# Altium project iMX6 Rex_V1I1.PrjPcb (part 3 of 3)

## Sheet [13] - ETHERNET PHY.SchDoc
size A2; DocumentNumber: 13; SheetNumber: 13; SheetTotal: 20
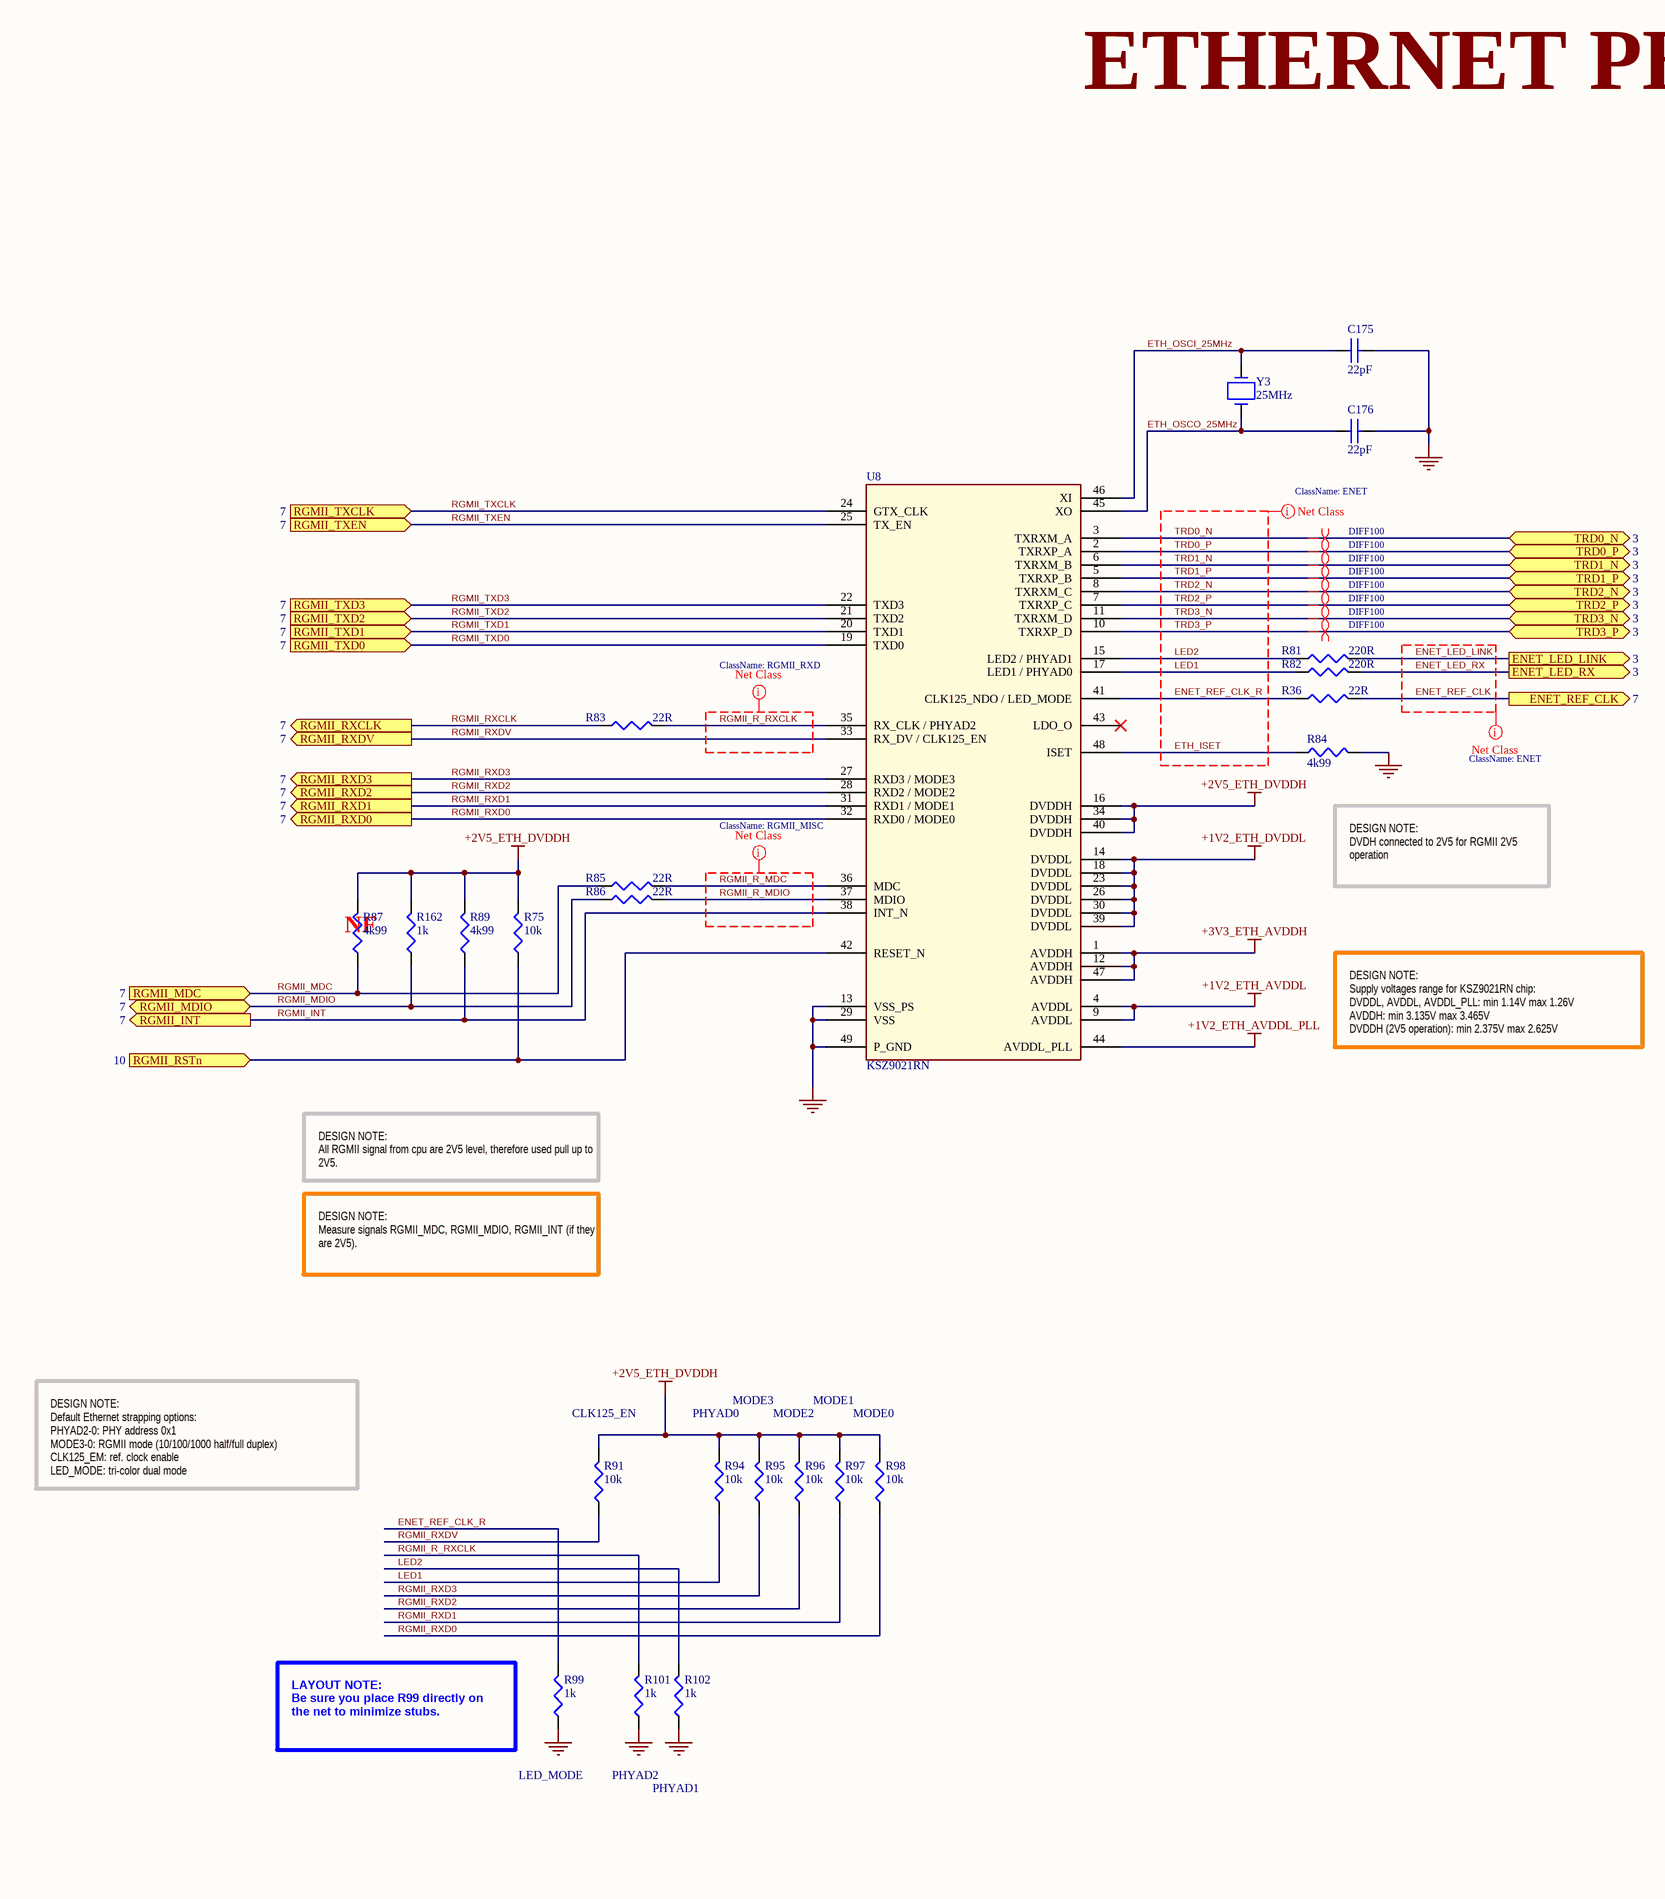
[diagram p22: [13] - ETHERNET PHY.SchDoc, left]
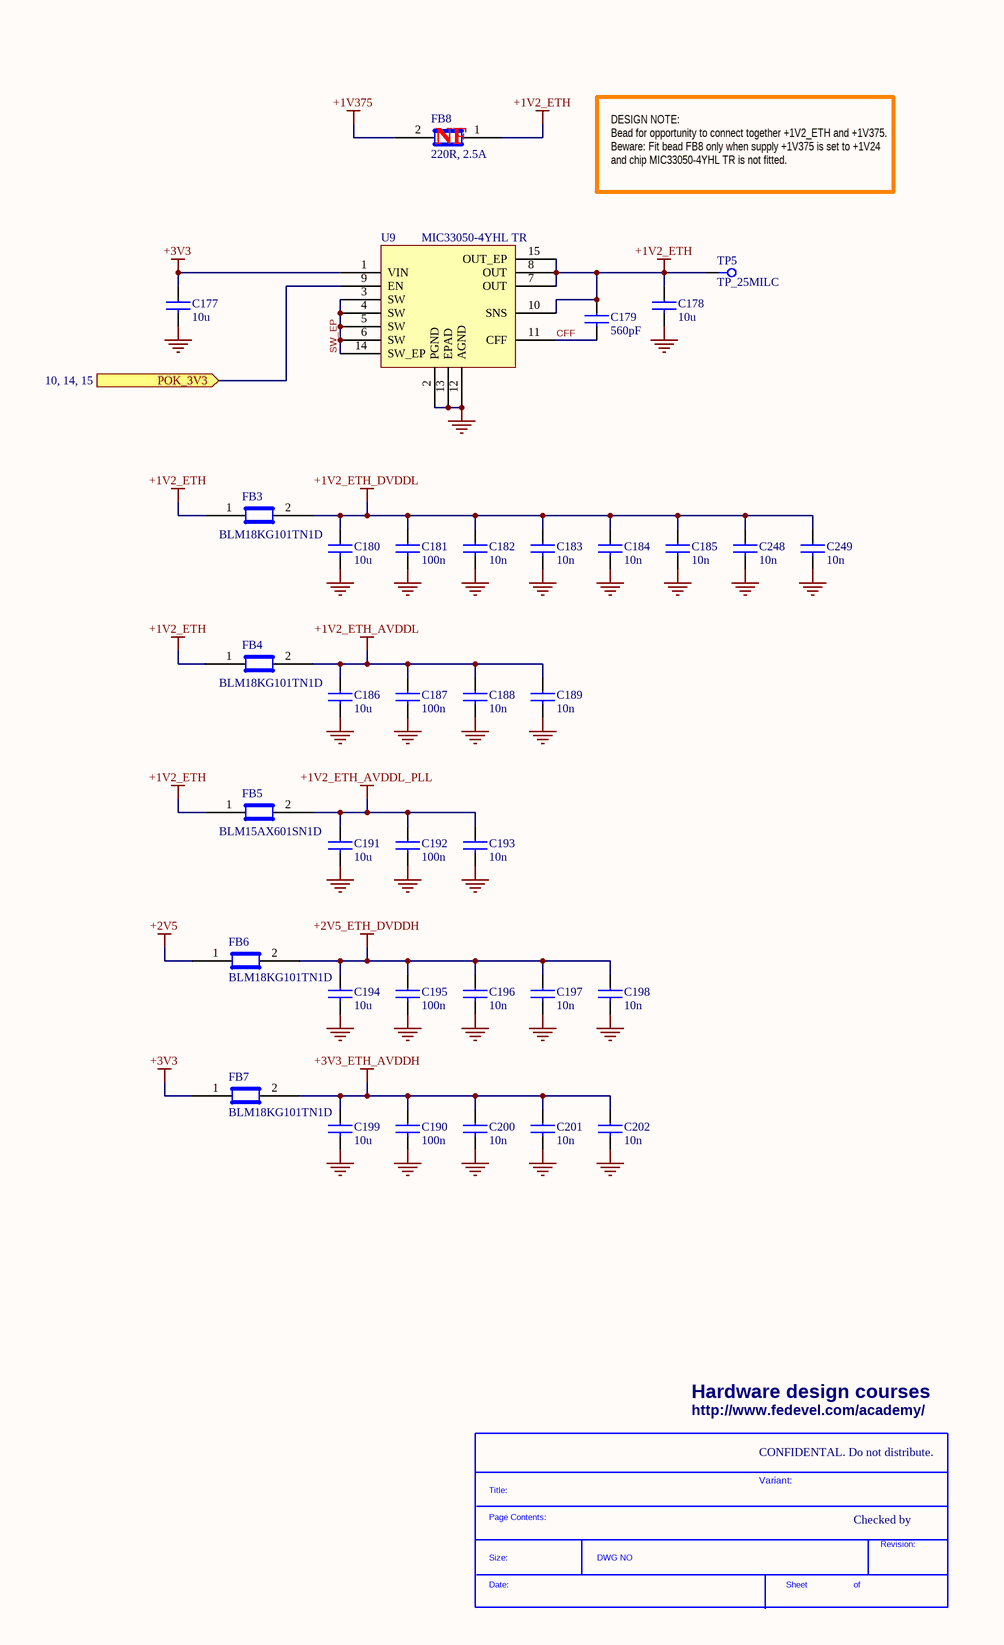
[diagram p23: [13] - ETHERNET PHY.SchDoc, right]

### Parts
(Parts that share a designator on the sheet are numbered #1, #2 ... from top to bottom, then left to right.)
*#15  SDTitleBlock  (value not drawn)  (graphical)
C175  22pF  [C0402]
C176  22pF  [C0402]
C177  10u  [C0603]
C178  10u  [C0603]
C179  560pF  [C0402]
C180  10u  [C0603]
C181  100n  [C0402]
C182  10n  [C0402]
C183  10n  [C0402]
C184  10n  [C0402]
C185  10n  [C0402]
C186  10u  [C0603]
C187  100n  [C0402]
C188  10n  [C0402]
C189  10n  [C0402]
C190  100n  [C0402]
C191  10u  [C0603]
C192  100n  [C0402]
C193  10n  [C0402]
C194  10u  [C0603]
C195  100n  [C0402]
C196  10n  [C0402]
C197  10n  [C0402]
C198  10n  [C0402]
C199  10u  [C0603]
C200  10n  [C0402]
C201  10n  [C0402]
C202  10n  [C0402]
C248  10n  [C0402]
C249  10n  [C0402]
FB3  BLM18KG101TN1D  [C0603]
FB4  BLM18KG101TN1D  [C0603]
FB5  BLM15AX601SN1D  [C0402]
FB6  BLM18KG101TN1D  [C0603]
FB7  BLM18KG101TN1D  [C0603]
FB8  220R, 2.5A  [C0603]
R36  22R  [R0402]
R75  10k  [R0402]
R81  220R  [R0402]
R82  220R  [R0402]
R83  22R  [R0402]
R84  4k99  [R0402]
R85  22R  [R0402]
R86  22R  [R0402]
R87  4k99  [R0402]
R89  4k99  [R0402]
R91  10k  [R0402]
R94  10k  [R0402]
R95  10k  [R0402]
R96  10k  [R0402]
R97  10k  [R0402]
R98  10k  [R0402]
R99  1k  [R0402]
R101  1k  [R0402]
R102  1k  [R0402]
R162  1k  [R0402]
TP5  TP_25MILC  [TP_25C]  (no BOM)
U8  KSZ9021RN  [QFN48_7MMX7MM]
U9  MIC33050-4YHL TR  [MLF_3x3_12PINS]
Y3  25MHz  [ABM7_v1_1]

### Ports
ENET_LED_LINK (out, see 3), ENET_LED_RX (out, see 3), ENET_REF_CLK (out, see 7), POK_3V3 (see 10, 14, 15), RGMII_INT (out, see 7), RGMII_MDC (in, see 7), RGMII_MDIO (bidir, see 7), RGMII_RSTn (in, see 10), RGMII_RXCLK (out, see 7), RGMII_RXD0 (out, see 7), RGMII_RXD1 (out, see 7), RGMII_RXD2 (out, see 7), RGMII_RXD3 (out, see 7), RGMII_RXDV (out, see 7), RGMII_TXCLK (in, see 7), RGMII_TXD0 (in, see 7), RGMII_TXD1 (in, see 7), RGMII_TXD2 (in, see 7), RGMII_TXD3 (in, see 7), RGMII_TXEN (in, see 7), TRD0_N (bidir, see 3), TRD0_P (bidir, see 3), TRD1_N (bidir, see 3), TRD1_P (bidir, see 3), TRD2_N (bidir, see 3), TRD2_P (bidir, see 3), TRD3_N (bidir, see 3), TRD3_P (bidir, see 3)

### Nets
+1V2_ETH: C178.1 C179.1 FB3.1 FB4.1 FB5.1 FB8.1 TP5.1 U9.7(OUT) U9.8(OUT) U9.10(SNS) U9.15(OUT_EP)
+1V2_ETH_AVDDL: C186.1 C187.1 C188.1 C189.1 FB4.2 U8.4(AVDDL) U8.9(AVDDL)
+1V2_ETH_AVDDL_PLL: C191.1 C192.1 C193.1 FB5.2 U8.44(AVDDL_PLL)
+1V2_ETH_DVDDL: C180.1 C181.1 C182.1 C183.1 C184.1 C185.1 C248.1 C249.1 FB3.2 U8.14(DVDDL) U8.18(DVDDL) U8.23(DVDDL) U8.26(DVDDL) U8.30(DVDDL) U8.39(DVDDL)
+1V375: FB8.2
+2V5: FB6.1
+2V5_ETH_DVDDH: C194.1 C195.1 C196.1 C197.1 C198.1 FB6.2 R75.2 R87.2 R89.2 R91.2 R94.2 R95.2 R96.2 R97.2 R98.2 R162.2 U8.16(DVDDH) U8.34(DVDDH) U8.40(DVDDH)
+3V3: C177.1 FB7.1 U9.1(VIN)
+3V3_ETH_AVDDH: C190.1 C199.1 C200.1 C201.1 C202.1 FB7.2 U8.1(AVDDH) U8.12(AVDDH) U8.47(AVDDH)
GND: C175.2 C176.2 C177.2 C178.2 C180.2 C181.2 C182.2 C183.2 C184.2 C185.2 C186.2 C187.2 C188.2 C189.2 C190.2 C191.2 C192.2 C193.2 C194.2 C195.2 C196.2 C197.2 C198.2 C199.2 C200.2 C201.2 C202.2 C248.2 C249.2 R84.2 R99.1 R101.1 R102.1 U8.13(VSS_PS) U8.29(VSS) U8.49(P_GND) U9.2(PGND) U9.12(AGND) U9.13(EPAD)
CFF: C179.2 U9.11(CFF)
ENET_LED_LINK: R81.2 ; port ENET_LED_LINK
ENET_LED_RX: R82.2 ; port ENET_LED_RX
ENET_REF_CLK: R36.2 ; port ENET_REF_CLK
ENET_REF_CLK_R: R36.1 R99.2 U8.41(CLK125_NDO_/_LED_MODE)
ETH_ISET: R84.1 U8.48(ISET)
ETH_OSCI_25MHz: C175.1 U8.46(XI) Y3.2
ETH_OSCO_25MHz: C176.1 U8.45(XO) Y3.1
LED1: R82.1 R94.1 U8.17(LED1_/_PHYAD0)
LED2: R81.1 R102.2 U8.15(LED2_/_PHYAD1)
POK_3V3: U9.9(EN) ; port POK_3V3
RGMII_INT: R89.1 U8.38(INT_N) ; port RGMII_INT
RGMII_MDC: R85.1 R87.1 ; port RGMII_MDC
RGMII_MDIO: R86.1 R162.1 ; port RGMII_MDIO
RGMII_R_MDC: R85.2 U8.36(MDC)
RGMII_R_MDIO: R86.2 U8.37(MDIO)
RGMII_R_RXCLK: R83.2 R101.2 U8.35(RX_CLK_/_PHYAD2)
RGMII_RSTn: R75.1 U8.42(RESET_N) ; port RGMII_RSTn
RGMII_RXCLK: R83.1 ; port RGMII_RXCLK
RGMII_RXD0: R98.1 U8.32(RXD0_/_MODE0) ; port RGMII_RXD0
RGMII_RXD1: R97.1 U8.31(RXD1_/_MODE1) ; port RGMII_RXD1
RGMII_RXD2: R96.1 U8.28(RXD2_/_MODE2) ; port RGMII_RXD2
RGMII_RXD3: R95.1 U8.27(RXD3_/_MODE3) ; port RGMII_RXD3
RGMII_RXDV: R91.1 U8.33(RX_DV_/_CLK125_EN) ; port RGMII_RXDV
RGMII_TXCLK: U8.24(GTX_CLK) ; port RGMII_TXCLK
RGMII_TXD0: U8.19(TXD0) ; port RGMII_TXD0
RGMII_TXD1: U8.20(TXD1) ; port RGMII_TXD1
RGMII_TXD2: U8.21(TXD2) ; port RGMII_TXD2
RGMII_TXD3: U8.22(TXD3) ; port RGMII_TXD3
RGMII_TXEN: U8.25(TX_EN) ; port RGMII_TXEN
SW_EP: U9.3(SW) U9.4(SW) U9.5(SW) U9.6(SW) U9.14(SW_EP)
TRD0_N: U8.3(TXRXM_A) ; port TRD0_N
TRD0_P: U8.2(TXRXP_A) ; port TRD0_P
TRD1_N: U8.6(TXRXM_B) ; port TRD1_N
TRD1_P: U8.5(TXRXP_B) ; port TRD1_P
TRD2_N: U8.8(TXRXM_C) ; port TRD2_N
TRD2_P: U8.7(TXRXP_C) ; port TRD2_P
TRD3_N: U8.11(TXRXM_D) ; port TRD3_N
TRD3_P: U8.10(TXRXP_D) ; port TRD3_P

Not connected (* = marked no-connect by the designer): U8 43(LDO_O)*

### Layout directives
differential pair; net class DIFF100: TRD0_N, TRD0_P, TRD1_N, TRD1_P, TRD2_N, TRD2_P, TRD3_N, TRD3_P
net class ENET: ENET_LED_LINK, ENET_LED_RX, ENET_REF_CLK, ENET_REF_CLK_R, ETH_ISET, LED1, LED2, TRD0_N, TRD0_P, TRD1_N, TRD1_P, TRD2_N, TRD2_P, TRD3_N, TRD3_P
net class RGMII_MISC: RGMII_R_MDC, RGMII_R_MDIO
net class RGMII_RXD: RGMII_R_RXCLK

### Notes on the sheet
- ETHERNET PHY
- (near FB8) NF
- DESIGN NOTE:
  Bead for opportunity to connect together +1V2_ETH and +1V375. Beware: Fit bead FB8 only when supply +1V375 is set to +1V24 and chip MIC33050-4YHL TR is not fitted.
- DESIGN NOTE:
  DVDH connected to 2V5 for RGMII 2V5 operation
- (near R87) NF
- DESIGN NOTE:
  Supply voltages range for KSZ9021RN chip:
  DVDDL, AVDDL, AVDDL_PLL: min 1.14V max 1.26V
  AVDDH: min 3.135V max 3.465V
  DVDDH (2V5 operation): min 2.375V max 2.625V
- DESIGN NOTE:
  All RGMII signal from cpu are 2V5 level, therefore used pull up to 2V5.
- DESIGN NOTE:
  Measure signals RGMII_MDC, RGMII_MDIO, RGMII_INT (if they are 2V5).
- (near R91) CLK125_EN
- PHYAD0
- MODE3
- MODE2
- MODE1
- MODE0
- DESIGN NOTE:
  Default Ethernet strapping options:
  PHYAD2-0: PHY address 0x1
  MODE3-0: RGMII mode (10/100/1000 half/full duplex)
  CLK125_EM: ref. clock enable
  LED_MODE: tri-color dual mode
- LAYOUT NOTE:
  Be sure you place R99 directly on the net to minimize stubs.
- LED_MODE
- PHYAD2
- Hardware design courses
- PHYAD1
- http://www.fedevel.com/academy/
- CONFIDENTAL. Do not distribute.
- Variant:
- Checked by

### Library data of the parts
C175 C176 = C1005C0G1H220J: CAP CER 22PF 50V C0G 5% 0402; Manufacturer: TDK Corporation; .Checked PCB: used; Description: CAP CER 22PF 50V 5% NP0 0402; Temperature Coefficient: C0G, NP0
C177 C178 C180 C186 C191 C194 C199 = C1608X5R0J106M: CAP CER 10UF 6.3V X5R 20% 0603; Manufacturer: TDK Corporation; Capacitance: 10µF; Value: 10µF; .Checked PCB: used; Description: CAP CER 10UF 6.3V 20% X5R 0603
C179 = GRM1555C1H561JA01D: CAP CER 560PF 50V C0G 0402; Manufacturer: Murata Electronics North America; .Checked PCB: used; Description: CAP CER 560PF 50V 5% NP0 0402; Tolerance: ±5%; Temperature Coefficient: C0G, NP0
C181 C187 C190 C192 C195 = C1005X5R1H104K: CAP CER .10UF 50V X5R 10% 0402; Manufacturer: TDK Corporation; Capacitance: 0.1µF; Value: 100nF; .Checked PCB: used; Description: CAP CER 0.1UF 50V 10% X5R 0402
C182-C185 C188 C189 C193 C196-C198 C200-C202 C248 C249 = C1005X7R1C103K: CAP CER 10000PF 16V X7R 10% 0402; Manufacturer: TDK Corporation; Value: 10nF; .Checked PCB: used; Description: CAP CER 10000PF 16V 10% X7R 0402
FB3 FB4 FB6 FB7 = BLM18KG101TN1D: FERRITE CHIP 100 OHM BEAD 0603 3A; Manufacturer: Murata Electronics North America; .Checked PCB: used; Impedance @ Frequency: 100 Ohm @ 100MHz; DC Resistance (DCR): 30 mOhm Max; Filter Type: Differential Mode - Single; Number of Lines: 1
FB5 = BLM15AX601SN1D: FERRITE CHIP 600 OHM 0402 420mA; Manufacturer: Murata Electronics North America; .Checked PCB: used; Impedance @ Frequency: 600 Ohm @ 100MHz; DC Resistance (DCR): 340 mOhm Max; Filter Type: Differential Mode - Single; Number of Lines: 1
FB8 = BLM18SG221TN1D: FERRITE CHIP 220 OHM 2500MA 0603; Manufacturer: Murata Electronics North America; Impedance @ Frequency: 220 Ohm @ 100MHz; DC Resistance (DCR): 40 mOhm Max; Filter Type: Differential Mode - Single; Number of Lines: 1; .Checked PCB: RF
R36 R83 R85 R86 = RC0402FR-0722RL: RES 22.0 OHM 1/16W 1% 0402 SMD; Manufacturer: Yageo; Resistance (Ohms): 22; Power (Watts): 0.063W, 1/16W; .Checked PCB: used; Temperature Coefficient: ±100ppm/°C
R75 R91 R94-R98 = RC0402FR-0710KL: RES 10.0K OHM 1/16W 1% 0402 SMD; Manufacturer: Yageo; Power (Watts): 0.063W, 1/16W; .Checked PCB: used; Temperature Coefficient: ±100ppm/°C
R81 R82 = RC0402FR-07220RL: RES 220 OHM 1/16W 1% 0402 SMD; Manufacturer: Yageo; Resistance (Ohms): 220; Power (Watts): 0.063W, 1/16W; .Checked PCB: used; Temperature Coefficient: ±100ppm/°C
R84 R87 R89 = RMCF0402FT4K99: RES TF 4.99K OHM 1% 1/16W 0402; Manufacturer: Stackpole Electronics Inc; Power (Watts): 0.063W, 1/16W; .Checked PCB: used; Temperature Coefficient: ±100ppm/°C
R99 R101 R102 R162 = RC0402FR-071KL: RES 1.00K OHM 1/16W 1% 0402 SMD; Manufacturer: Yageo; Power (Watts): 0.063W, 1/16W; .Checked PCB: used; Temperature Coefficient: ±100ppm/°C
TP5 = TP_25MILC: Test Point 25mil
U8 = KSZ9021RN: IC TXRX 10/100/1000 SGL 48QFN; Manufacturer: Micrel Inc; Number of Drivers/Receivers: 8/8; Protocol: Gigabit Ethernet; Voltage - Supply: 3.135 V ~ 3.465 V; .Creator: MM; .Checked PCB: MM, checked by RF
U9 = MIC33050-4YHL TR: IC PWM REG 600mA 1.2V 12-MLF; Manufacturer: Micrel Inc; .Checked PCB: used; Voltage - Input: 2.7 V ~ 5.5 V; Description: IC BUCK SYNC 1.2V 0.6A 12MLF; Output Type: Fixed; Number of Outputs: 1; PWM Type: Current Mode; Frequency - Switching: 4MHz; Synchronous Rectifier: Yes
Y3 = ABM7-25.000MHZ-D-2-Y-T V1.1: CRYSTAL 25.0000 MHZ 18PF SMD; Manufacturer: Abracon Corporation; .Checked PCB: RF used by MM; Frequency Stability: ±30ppm; Frequency Tolerance: ±20ppm; Operating Mode: Fundamental; .V1.1: footprint & comment updated

## Sheet [14] - SPI FLASH, LEDS.SchDoc
size A2; DocumentNumber: 14; SheetNumber: 14; SheetTotal: 20
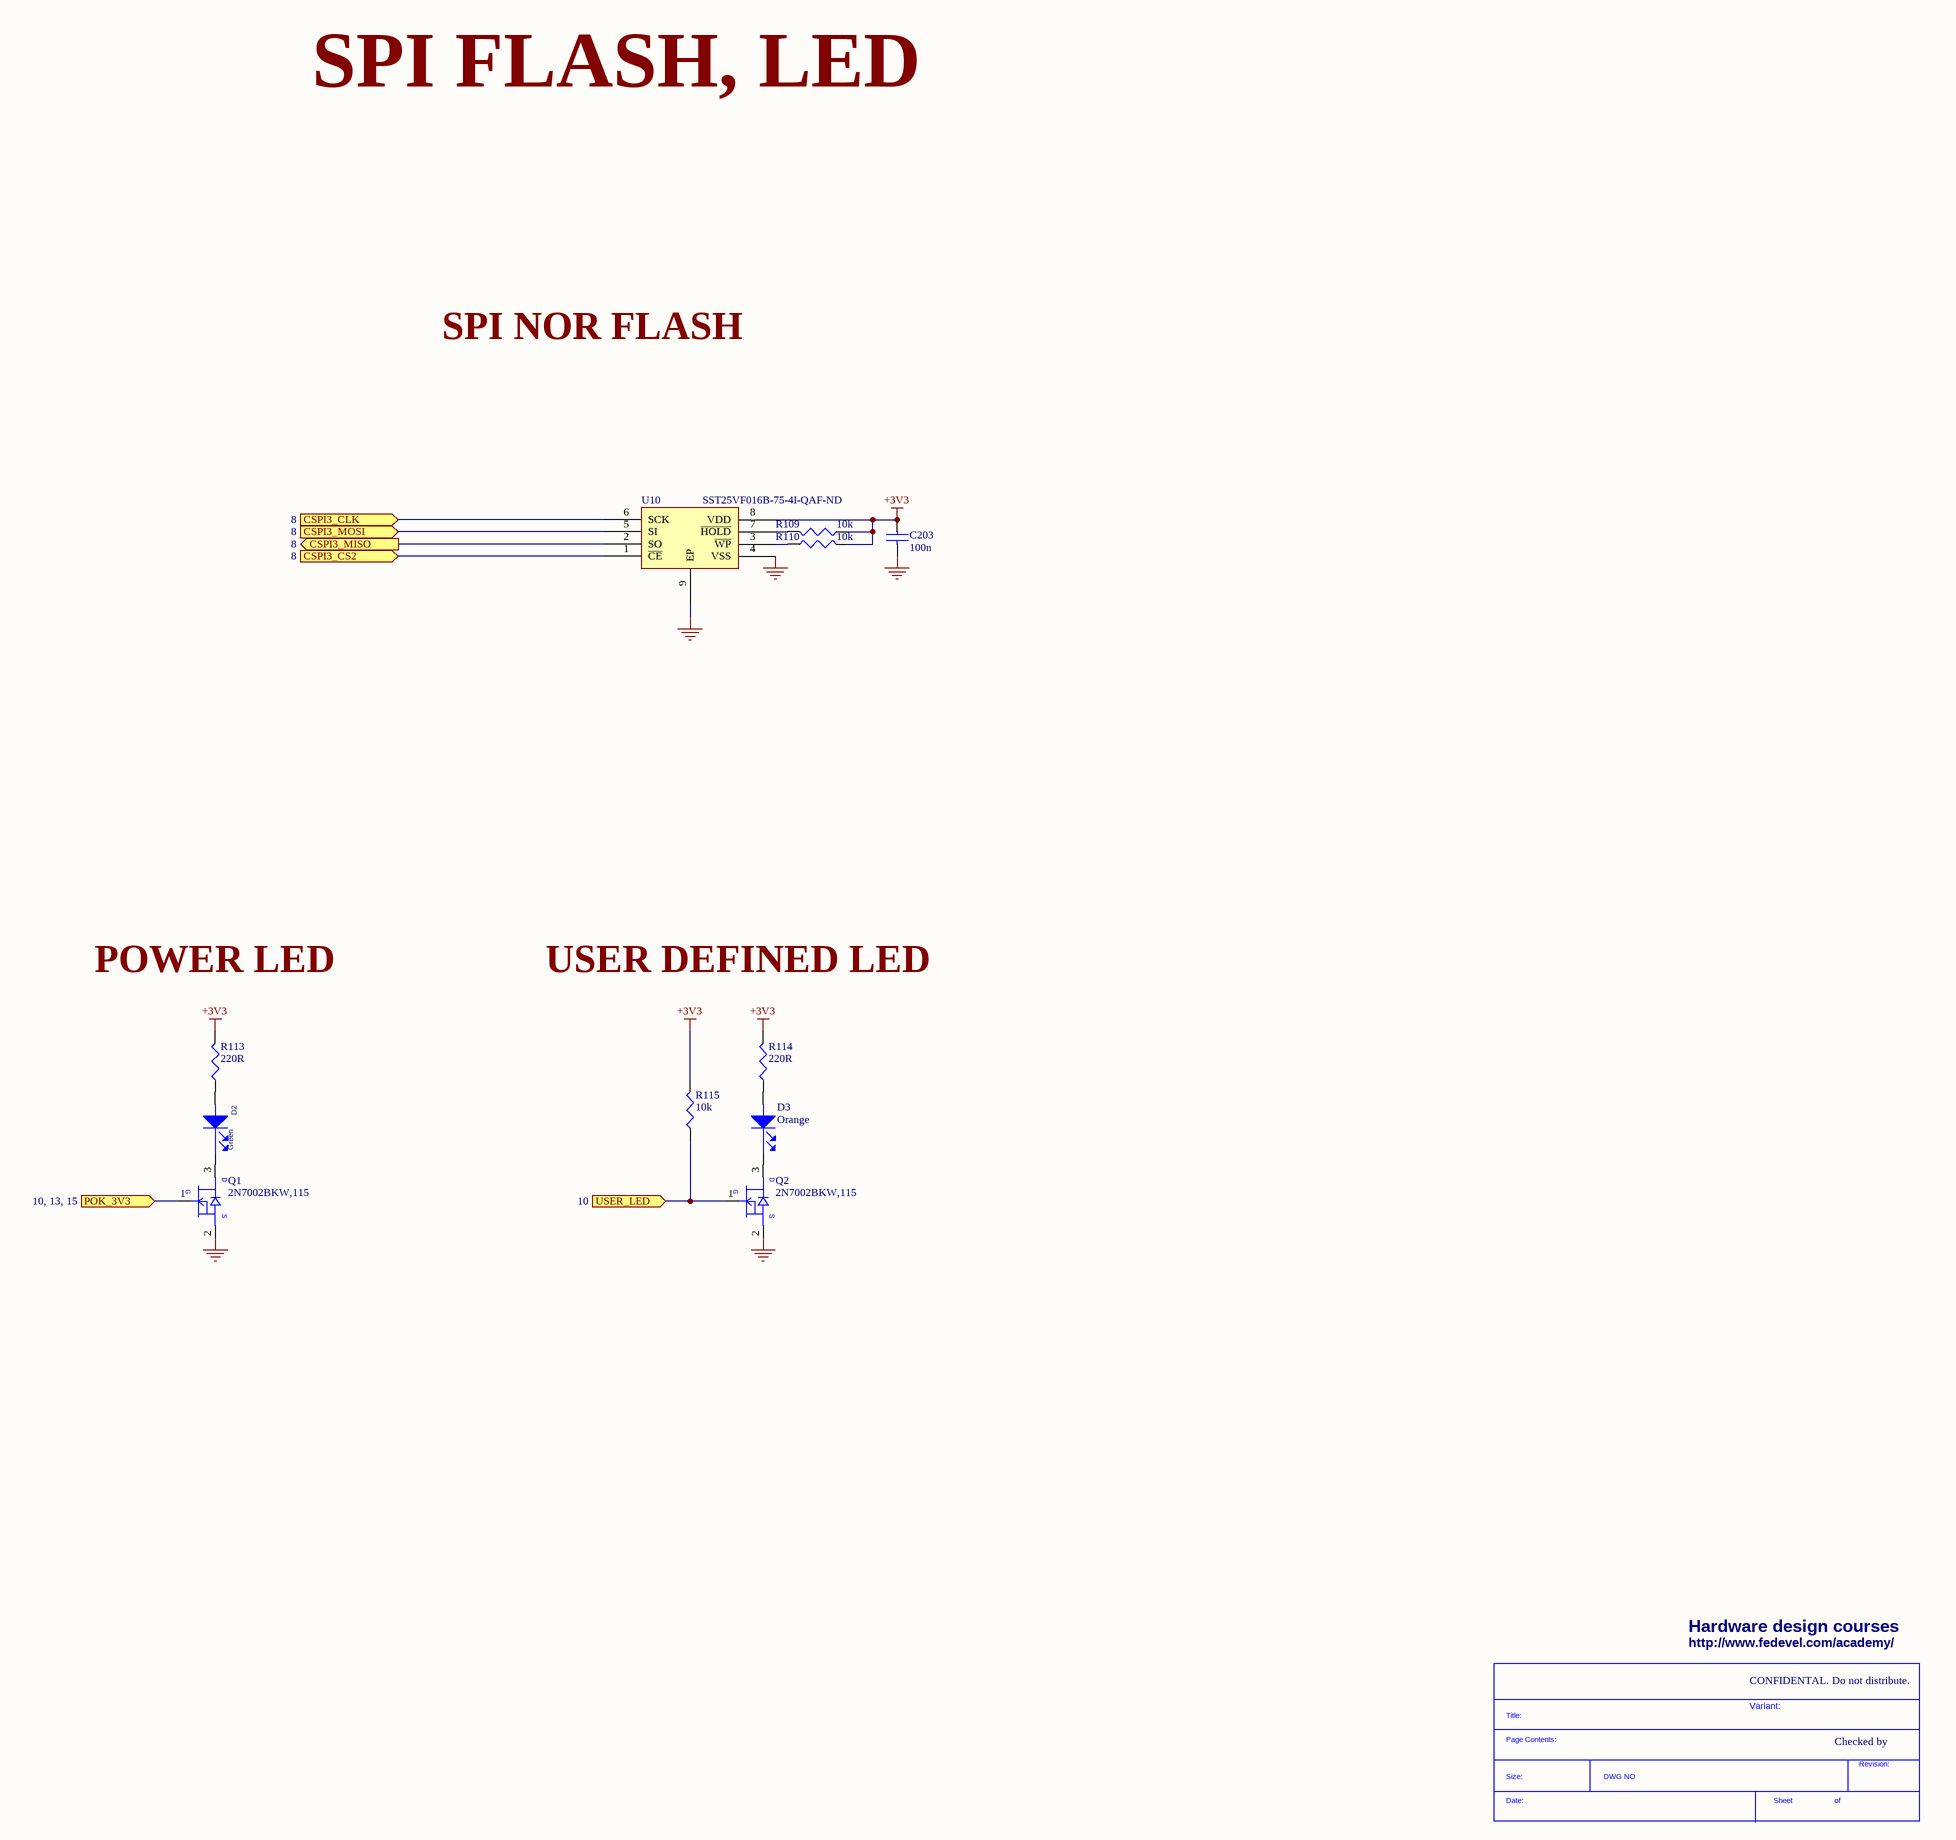
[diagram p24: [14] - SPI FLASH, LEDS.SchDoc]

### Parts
(Parts that share a designator on the sheet are numbered #1, #2 ... from top to bottom, then left to right.)
*#16  SDTitleBlock  (value not drawn)  (graphical)
C203  100n  [C0402]
D2  Green  [LED_0603]
D3  Orange  [LED_0603]
Q1  2N7002BKW,115  [SC70_SOT323]
Q2  2N7002BKW,115  [SC70_SOT323]
R109  10k  [R0402]
R110  10k  [R0402]
R113  220R  [R0402]
R114  220R  [R0402]
R115  10k  [R0402]
U10  SST25VF016B-75-4I-QAF-ND  [WSON8_6X5MM]

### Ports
CSPI3_CLK (in, see 8), CSPI3_CS2 (in, see 8), CSPI3_MISO (out, see 8), CSPI3_MOSI (in, see 8), POK_3V3 (see 10, 13, 15), USER_LED (in, see 10)

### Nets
+3V3: C203.1 R109.1 R110.2 R113.2 R114.2 R115.2 U10.8(VDD)
GND: C203.2 Q1.2(SOURCE) Q2.2(SOURCE) U10.4(VSS) U10.9(EP)
CSPI3_CLK: U10.6(SCK) ; port CSPI3_CLK
CSPI3_CS2: U10.1(~{CE}) ; port CSPI3_CS2
CSPI3_MISO: U10.2(SO) ; port CSPI3_MISO
CSPI3_MOSI: U10.5(SI) ; port CSPI3_MOSI
POK_3V3: Q1.1(GATE) ; port POK_3V3
USER_LED: Q2.1(GATE) R115.1 ; port USER_LED
NetD2_1: D2.1(cathode) Q1.3(DRAIN)
NetD2_2: D2.2(ANODE) R113.1
NetD3_1: D3.1(cathode) Q2.3(DRAIN)
NetD3_2: D3.2(ANODE) R114.1
NetR109_2: R109.2 U10.7(~{HOLD})
NetR110_1: R110.1 U10.3(~{WP})

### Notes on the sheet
- SPI FLASH, LED
- SPI NOR FLASH
- POWER LED
- USER DEFINED LED
- Hardware design courses
- http://www.fedevel.com/academy/
- CONFIDENTAL. Do not distribute.
- Variant:
- Checked by

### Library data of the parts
C203 = C1005X5R1H104K: as C181 on sheet [13] - ETHERNET PHY
D2 = LG L29K-G2J1-24-Z: LED SMARTLED GREEN 570NM 0603; Manufacturer: OSRAM Opto Semiconductors Inc; .Checked PCB: used; Current - Test: 2mA; Voltage - Forward (Vf) Typ: 1.7V; Luminous Flux @ Current - Test: 12 mlm; Millicandela Rating: 3.92mcd; Wavelength - Peak: 572nm; Lens Type: Diffused; Lens Style/Size: Rectangle with Flat Top, 1.3mm x 0.8mm; Viewing Angle: 160°; Regulator Topology: Positive Fixed; Voltage - Output: 2.5V; Voltage - Input: 2.6 V ~ 6 V; Voltage - Dropout (Typical): 0.16V @ 500mA; Number of Regulators: 1; Current - Output: 500mA; Current - Limit (Min): 600mA
D3 = LO L29K-H2K1-24-Z: LED SMARTLED ORANGE 606NM 0603; Manufacturer: OSRAM Opto Semiconductors Inc; Millicandela Rating: 6.3mcd; Voltage - Forward (Vf) Typ: 1.8V; Current - Test: 2mA; Wavelength - Peak: 610nm; Viewing Angle: 160°; Lens Type: Diffused; Lens Style/Size: Rectangle with Flat Top, 1.3mm x 0.8mm; Luminous Flux @ Current - Test: 25 mlm; .Checked PCB: RF
Q1 Q2 = 2N7002BKW,115: MOSFET N-CH 60V 310MA SOT323; Manufacturer: NXP Semiconductors; FET Type: MOSFET N-Channel, Metal Oxide; FET Feature: Logic Level Gate; Rds On (Max) @ Id, Vgs: 1.6 Ohm @ 500mA, 10V; Vgs(th) (Max) @ Id: 2.1V @ 250µA; Gate Charge (Qg) @ Vgs: 0.6nC @ 4.5V; Input Capacitance (Ciss) @ Vds: 50pF @ 10V; Power - Max: 275mW; .Checked PCB: RF
R109 R110 R115 = RC0402FR-0710KL: as R75 on sheet [13] - ETHERNET PHY
R113 R114 = RC0402FR-07220RL: as R81 on sheet [13] - ETHERNET PHY
U10 = SST25VF016B-75-4I-QAF: IC FLASH 16MBIT 75MHZ 8WSON; Manufacturer: Microchip Technology; Memory Size: 16M (2M x 8); Interface: SPI Serial; Voltage - Supply: 2.7 V ~ 3.6 V; .Creator: MM; .Checked PCB: MM, checked by RF

## Sheet [15] - PWR 3V3, 1V375.SchDoc
size A2; DocumentNumber: 15; SheetNumber: 15; SheetTotal: 20
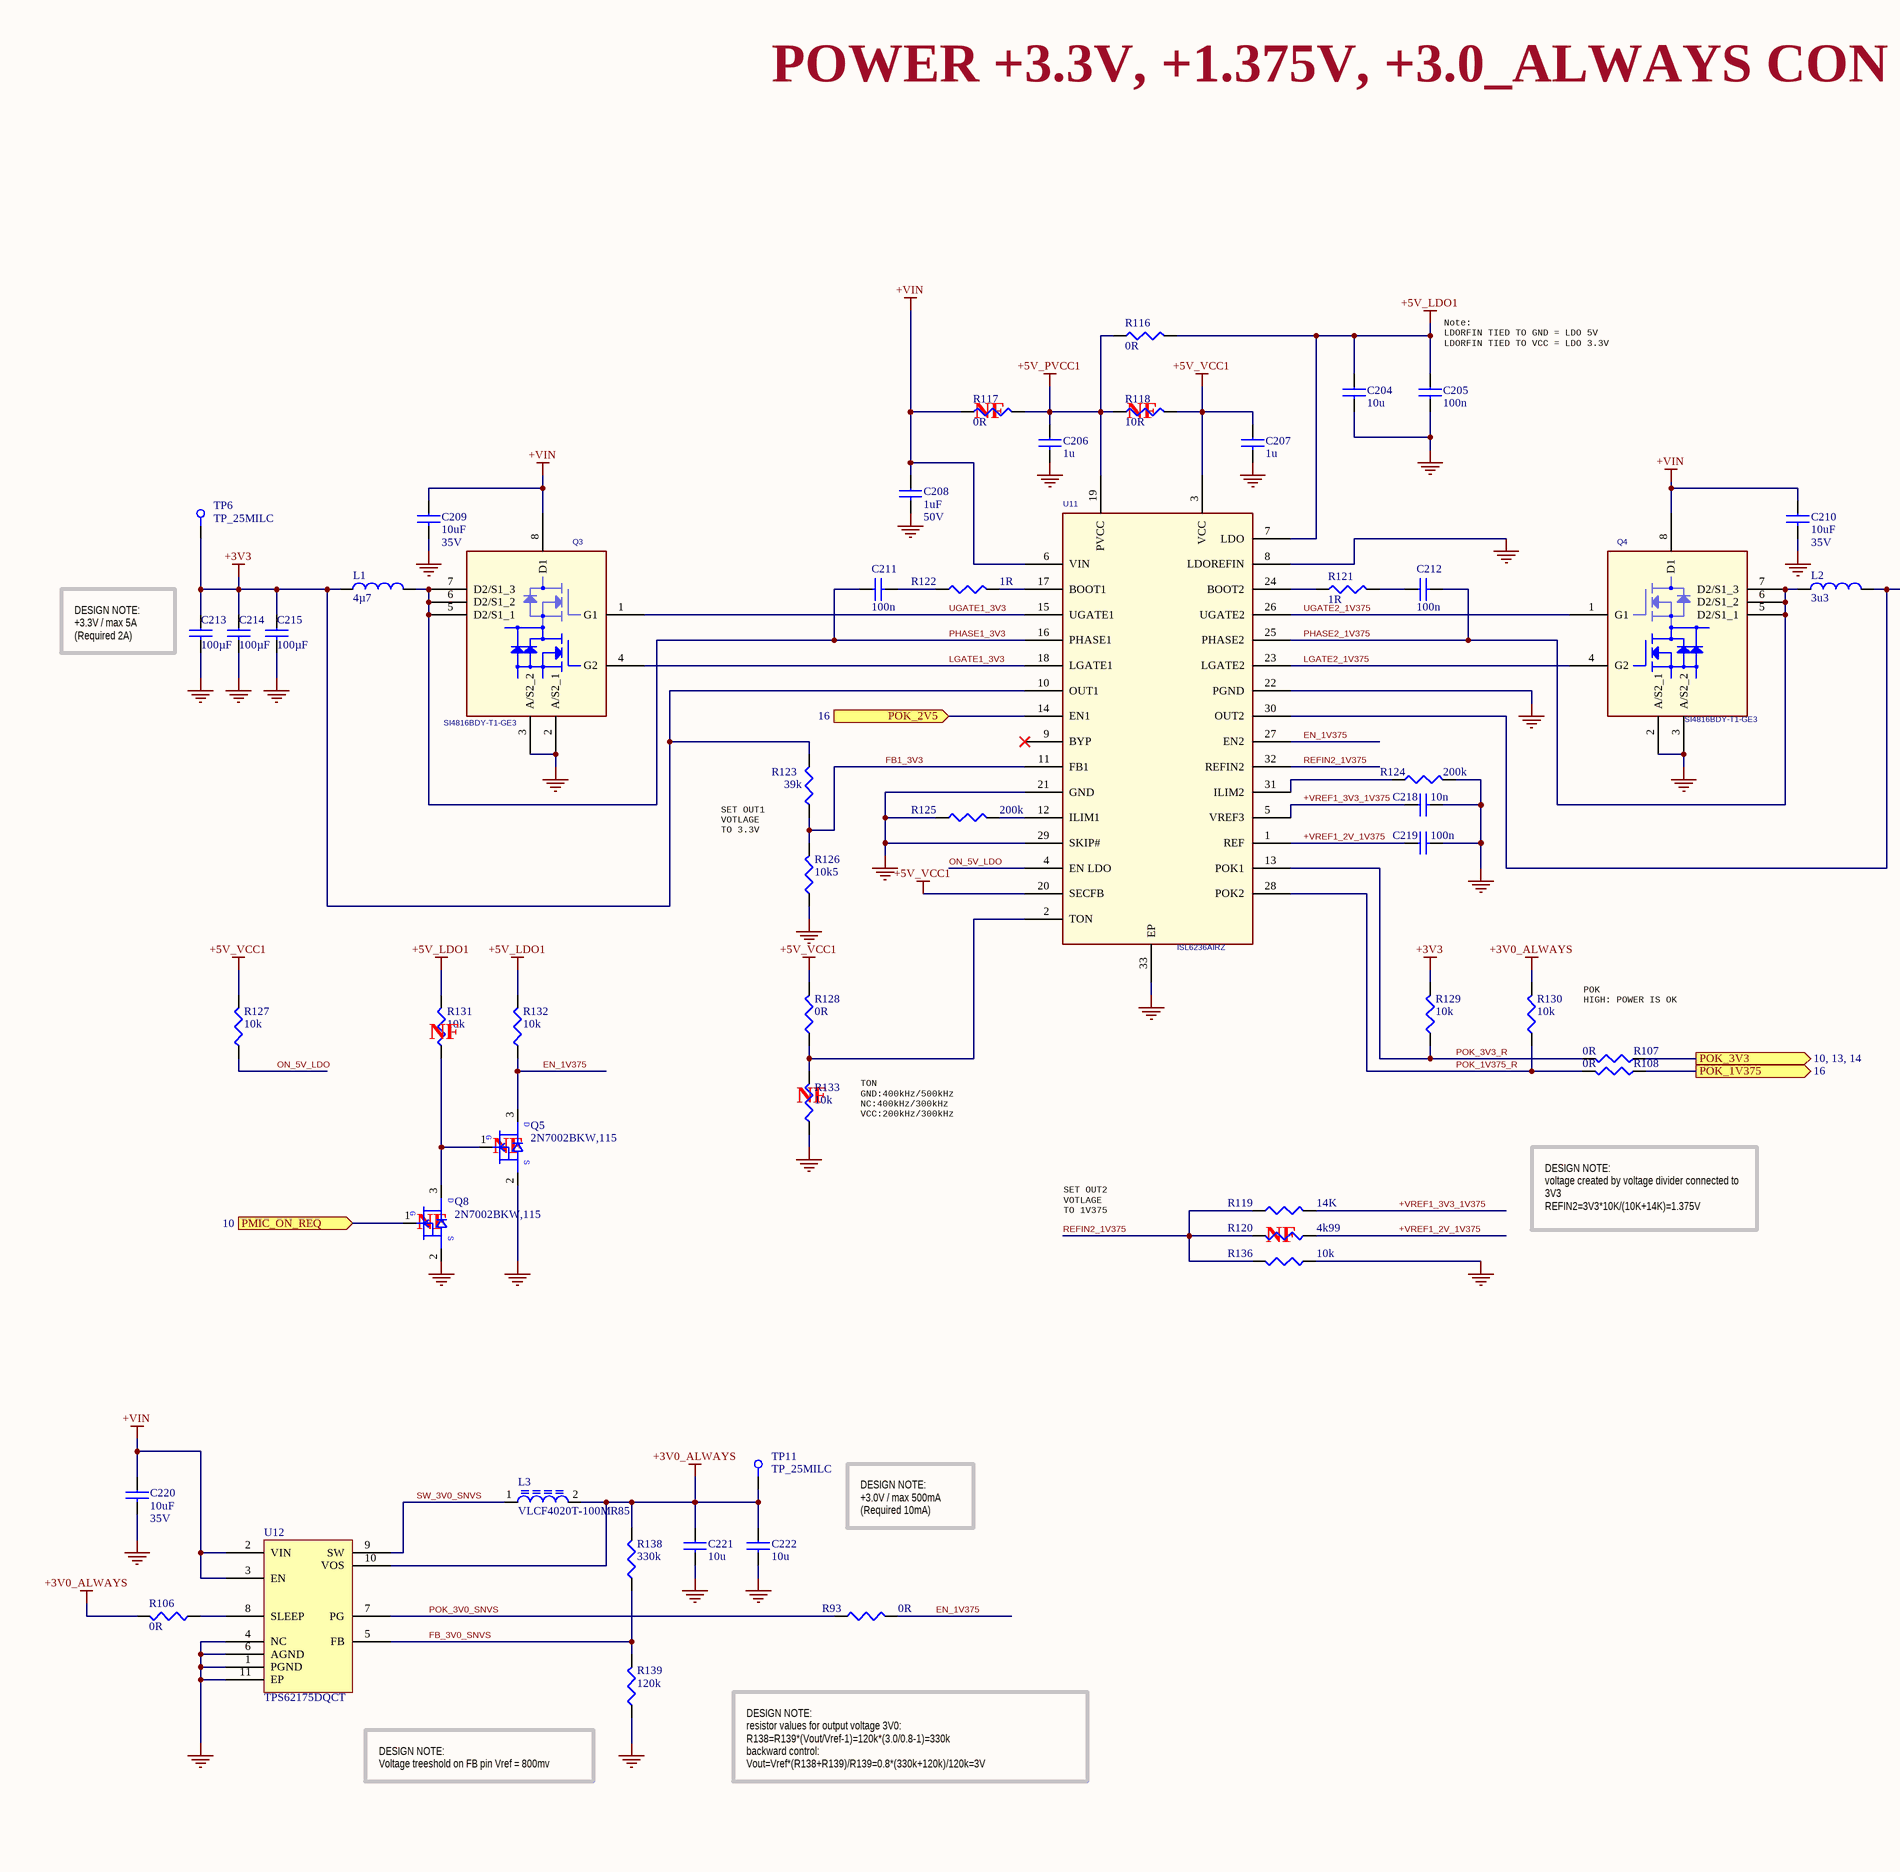
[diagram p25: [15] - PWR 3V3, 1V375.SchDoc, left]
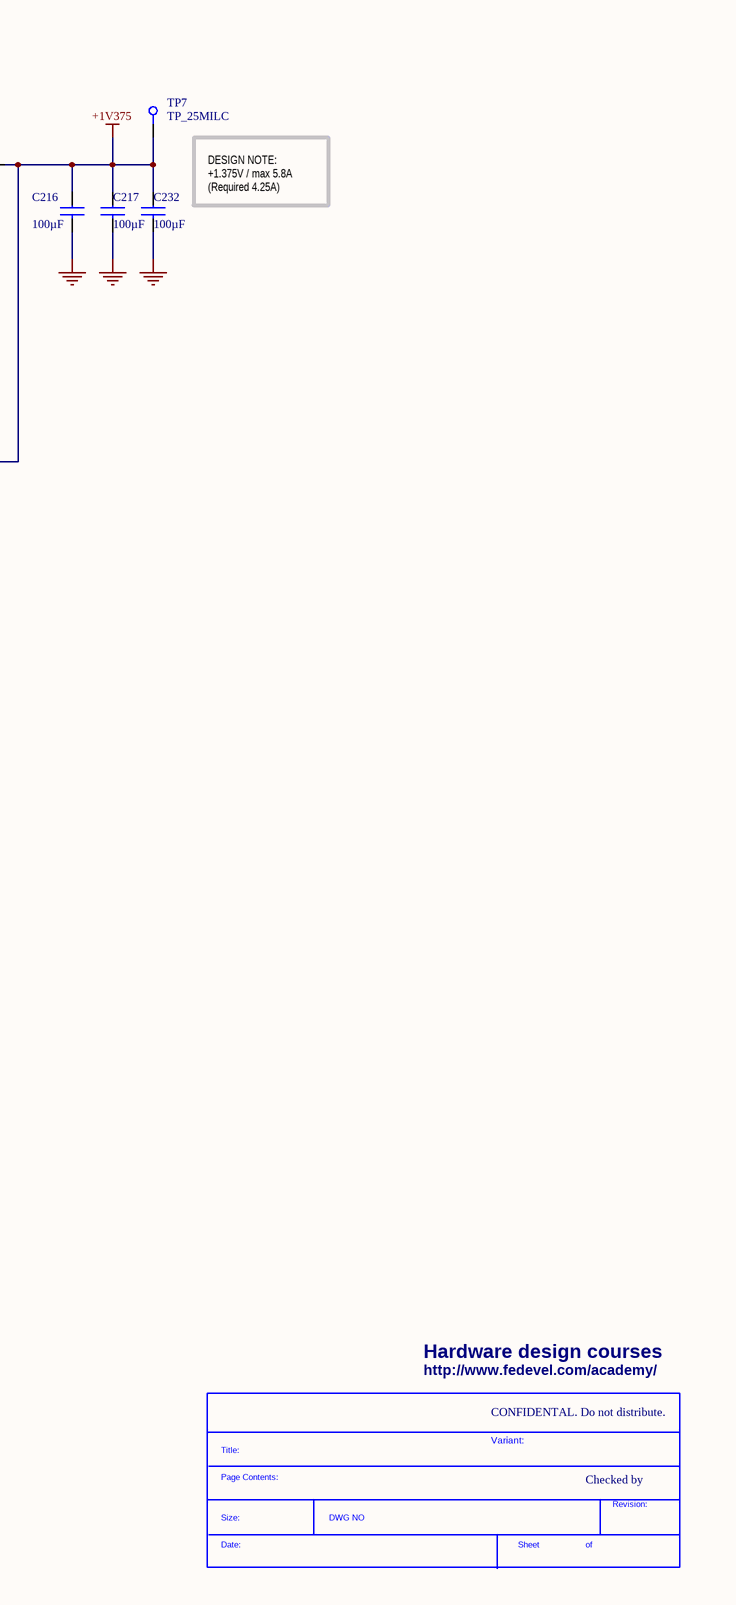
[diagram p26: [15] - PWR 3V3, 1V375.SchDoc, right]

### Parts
(Parts that share a designator on the sheet are numbered #1, #2 ... from top to bottom, then left to right.)
*#17  SDTitleBlock  (value not drawn)  (graphical)
C204  10u  [C0603]
C205  100n  [C0402]
C206  1u  [C0402]
C207  1u  [C0402]
C208  1uF  Voltage - Rated: 50V  [C0805]
C209  10uF  Voltage - Rated: 35V  [C1206]
C210  10uF  Voltage - Rated: 35V  [C1206]
C211  100n  [C0402]
C212  100n  [C0402]
C213  100µF  [C1206]
C214  100µF  [C1206]
C215  100µF  [C1206]
C216  100µF  [C1206]
C217  100µF  [C1206]
C218  10n  [C0402]
C219  100n  [C0402]
C220  10uF  Voltage - Rated: 35V  [C1206]
C221  10u  [C0603]
C222  10u  [C0603]
C232  100µF  [C1206]
L1  4µ7  [IHLP_255MILx270MIL]
L2  3u3  [IHLP_255MILx270MIL]
L3  VLCF4020T-100MR85  [VLCF4020]
Q3  SI4816BDY-T1-GE3  [8_SOIC_3.9MM]
Q4  SI4816BDY-T1-GE3  [8_SOIC_3.9MM]
Q5  2N7002BKW,115  [SC70_SOT323]
Q8  2N7002BKW,115  [SC70_SOT323]
R93  0R  [R0402]
R106  0R  [R0402]
R107  0R  [R0402]
R108  0R  [R0402]
R116  0R  [R0402]
R117  0R  [R0402]
R118  10R  [R0402]
R119  14K  [R0402]
R120  4k99  [R0402]
R121  1R  [R0402]
R122  1R  [R0402]
R123  39k  [R0402]
R124  200k  [R0402]
R125  200k  [R0402]
R126  10k5  [R0402]
R127  10k  [R0402]
R128  0R  [R0402]
R129  10k  [R0402]
R130  10k  [R0402]
R131  10k  [R0402]
R132  10k  [R0402]
R133  10k  [R0402]
R136  10k  [R0402]
R138  330k  [R0402]
R139  120k  [R0402]
TP6  TP_25MILC  [TP_25C]  (no BOM)
TP7  TP_25MILC  [TP_25C]  (no BOM)
TP11  TP_25MILC  [TP_25C]  (no BOM)
U11  ISL6236AIRZ  [32_VFQFN_EXPOSED_PAD]
U12  TPS62175DQCT  [DQC_PWSON-N10]

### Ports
PMIC_ON_REQ (in, see 10), POK_1V375 (out, see 16), POK_2V5 (in, see 16), POK_3V3 (see 10, 13, 14)

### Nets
+1V375: C216.1 C217.1 C232.1 L2.2 TP7.1 U11.30(OUT2)
+3V0_ALWAYS: C221.1 C222.1 L3.2 R106.2 R130.2 R138.2 TP11.1 U12.10(VOS)
+3V3: C213.1 C214.1 C215.1 L1.1 R123.2 R129.2 TP6.1 U11.10(OUT1)
+5V_LDO1: C204.1 C205.1 R116.2 R131.2 R132.2 U11.7(LDO)
+5V_PVCC1: C206.1 R116.1 R117.2 R118.1 U11.19(PVCC)
+5V_VCC1: C207.1 R118.2 R127.2 R128.2 U11.3(VCC) U11.20(SECFB)
+VIN: C208.1 C209.1 C210.1 C220.1 Q3.8(D1) Q4.8(D1) R117.1 U11.6(VIN) U12.2(VIN) U12.3(EN)
GND: C204.2 C205.2 C206.2 C207.2 C208.2 C209.2 C210.2 C213.2 C214.2 C215.2 C216.2 C217.2 C218.2 C219.2 C220.2 C221.2 C222.2 C232.2 Q3.2(A/S2_1) Q3.3(A/S2_2) Q4.2(A/S2_1) Q4.3(A/S2_2) Q5.2(SOURCE) Q8.2(SOURCE) R124.2 R125.1 R126.1 R133.1 R136.1 R139.1 U11.8(LDOREFIN) U11.21(GND) U11.22(PGND) U11.29(SKIP#) U11.33(EP) U12.1(PGND) U12.4(NC) U12.6(AGND) U12.11(EP)
+VREF1_2V_1V375: C219.1 R120.1 U11.1(REF)
+VREF1_3V3_1V375: C218.1 R119.2 U11.5(VREF3)
EN_1V375: Q5.3(DRAIN) R93.2 R132.1 U11.27(EN2)
FB1_3V3: R123.1 R126.2 U11.11(FB1)
FB_3V0_SNVS: R138.1 R139.2 U12.5(FB)
LGATE1_3V3: Q3.4(G2) U11.18(LGATE1)
LGATE2_1V375: Q4.4(G2) U11.23(LGATE2)
ON_5V_LDO: R127.1 U11.4(EN_LDO)
PHASE1_3V3: C211.1 L1.2 Q3.5(D2/S1_1) Q3.6(D2/S1_2) Q3.7(D2/S1_3) U11.16(PHASE1)
PHASE2_1V375: C212.2 L2.1 Q4.5(D2/S1_1) Q4.6(D2/S1_2) Q4.7(D2/S1_3) U11.25(PHASE2)
PMIC_ON_REQ: Q8.1(GATE) ; port PMIC_ON_REQ
POK_1V375: R108.1 ; port POK_1V375
POK_1V375_R: R108.2 R130.1 U11.28(POK2)
POK_2V5: U11.14(EN1) ; port POK_2V5
POK_3V0_SNVS: R93.1 U12.7(PG)
POK_3V3: R107.1 ; port POK_3V3
POK_3V3_R: R107.2 R129.1 U11.13(POK1)
REFIN2_1V375: R119.1 R120.2 R136.2 U11.32(REFIN2)
SW_3V0_SNVS: L3.1 U12.9(SW)
UGATE1_3V3: Q3.1(G1) U11.15(UGATE1)
UGATE2_1V375: Q4.1(G1) U11.26(UGATE2)
NetC211_2: C211.2 R122.1
NetC212_1: C212.1 R121.2
NetQ5_1: Q5.1(GATE) Q8.3(DRAIN) R131.1
NetR106_1: R106.1 U12.8(SLEEP)
NetR121_1: R121.1 U11.24(BOOT2)
NetR122_2: R122.2 U11.17(BOOT1)
NetR124_1: R124.1 U11.31(ILIM2)
NetR125_2: R125.2 U11.12(ILIM1)
NetR128_1: R128.1 R133.2 U11.2(TON)

Not connected (* = marked no-connect by the designer): U11 9(BYP)*

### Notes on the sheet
- POWER +3.3V, +1.375V, +3.0_ALWAYS CON
- (near C205) Note:
  LDORFIN TIED TO GND = LDO 5V
  LDORFIN TIED TO VCC = LDO 3.3V
- (near R117) NF
- (near R118) NF
- (near C213) DESIGN NOTE:
  +3.3V / max 5A
  (Required 2A)
- DESIGN NOTE:
  +1.375V / max 5.8A
  (Required 4.25A)
- SET OUT1
  VOTLAGE
  TO 3.3V
- POK
  HIGH: POWER IS OK
- (near R131) NF
- (near R133) NF
- TON
  GND:400kHz/500kHz
  NC:400kHz/300kHz
  VCC:200kHz/300kHz
- (near Q5) NF
- (near Q8) NF
- SET OUT2
  VOTLAGE
  TO 1V375
- (near R120) NF
- DESIGN NOTE:
  voltage created by voltage divider connected to 3V3
  REFIN2=3V3*10K/(10K+14K)=1.375V
- DESIGN NOTE:
  +3.0V / max 500mA
  (Required 10mA)
- Hardware design courses
- DESIGN NOTE:
  Voltage treeshold on FB pin Vref = 800mv
- DESIGN NOTE:
  resistor values for output voltage 3V0:
  R138=R139*(Vout/Vref-1)=120k*(3.0/0.8-1)=330k
  backward control:
  Vout=Vref*(R138+R139)/R139=0.8*(330k+120k)/120k=3V
- http://www.fedevel.com/academy/
- CONFIDENTAL. Do not distribute.
- Variant:
- Checked by

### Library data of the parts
C204 C221 C222 = C1608X5R0J106M: as C177 on sheet [13] - ETHERNET PHY
C205 C211 C212 C219 = C1005X5R1H104K: as C181 on sheet [13] - ETHERNET PHY
C206 C207 = C1005X5R1C105K: CAP CER 1.0UF 16V X5R 0402; Manufacturer: TDK Corporation; Capacitance: 1.0µF; Value: 1uF; .Checked PCB: used; Description: CAP CER 1UF 16V 10% X5R 0402; Tolerance: ±10%
C208 = GRM21BR71H105KA12L: CAP CER 1UF 50V X7R 0805; Manufacturer: Murata Electronics North America; Capacitance: 1.0µF; .Checked PCB: used; Description: CAP CER 1UF 50V 10% X7R 0805; Tolerance: ±10%
C209 C210 C220 = GRM31CR6YA106KA12L: CAP CER 10UF 35V X5R 1206; Manufacturer: Murata Electronics North America; Capacitance: 10µF; .Checked PCB: used; Description: CAP CER 10UF 35V 10% X5R 1206; Tolerance: ±10%
C213-C217 C232 = C3216X5R1A107M: CAP CER 100UF 10V X5R 20% 1206; Manufacturer: TDK Corporation; .Checked PCB: used; Description: CAP CER 100UF 10V 20% X5R 1206
C218 = C1005X7R1C103K: as C182 on sheet [13] - ETHERNET PHY
L1 = IHLP2525CZER4R7M01: INDUCTOR POWER 4.7UH 5.5A SMD; Manufacturer: Vishay/Dale; .Checked PCB: used; Inductance: 4.7µH; Current - Saturation: 10A; Shielding: Shielded; DC Resistance (DCR): 40 mOhm Max; Tolerance: ±20%; Frequency - Test: 100kHz
L2 = IHLP2525CZER3R3M01: INDUCTOR POWER 3.3UH 6A SMD; Manufacturer: Vishay Dale; Inductance: 3.3µH; Current - Saturation: 13.5A; Tolerance: ±20%; Shielding: Shielded; DC Resistance (DCR): 30 mOhm Max; Frequency - Test: 100kHz; .Checked PCB: RF
L3 = VLCF4020T-100MR85: INDUCTOR POWER 10UH .85A SMD; Manufacturer: TDK Corporation; Inductance: 10µH; Current Rating: 850mA; Tolerance: ±20%; Shielding: Shielded; DC Resistance (DCR): 185 mOhm Max; Frequency - Test: 100kHz; .Creator: MM; .Checked PCB: MM, checked by RF
Q3 Q4 = SI4816BDY-T1-GE3: MOSFET DL N-CH 30V 6.8A 8-SOIC; Manufacturer: Vishay/Siliconix; .Checked PCB: used; FET Type: 2 N-Channel (Dual); FET Feature: Logic Level Gate; Rds On (Max) @ Id, Vgs: 18.5 mOhm @ 6.8A, 10V; Current - Continuous Drain (Id) @ 25° C: 5.8A, 8.2A; Vgs(th) (Max) @ Id: 3V @ 250µA; Power - Max: 1W, 1.25W; Gate Charge (Qg) @ Vgs: 10nC @ 5V
Q5 Q8 = 2N7002BKW,115: as Q1 on sheet [14] - SPI FLASH, LEDS
R93 R106-R108 R116 R117 R128 = RC0402JR-070RL: RES 0.0 OHM 1/16W 0402 SMD; Manufacturer: Yageo; Resistance (Ohms): 0.0; Power (Watts): 0.063W, 1/16W; Tolerance: Jumper; .Checked PCB: used
R118 = RC0402FR-0710RL: RES 10.0 OHM 1/16W 1% 0402 SMD; Manufacturer: Yageo; Resistance (Ohms): 10; Power (Watts): 0.063W, 1/16W; .Checked PCB: used; Temperature Coefficient: ±200ppm/°C
R119 = RC0402FR-0714KL: RES 14.0K OHM 1/16W 1% 0402 SMD; Manufacturer: Yageo; Power (Watts): 0.063W, 1/16W; Temperature Coefficient: ±100ppm/°C; .Checked PCB: RF, used by MM; .Checked SCH: MM, checked by RF; .Creator: MM
R120 = RMCF0402FT4K99: as R84 on sheet [13] - ETHERNET PHY
R121 R122 = RC0402FR-071RL: RES 1.00 OHM 1/16W 1% 0402 SM; Manufacturer: Yageo; Resistance (Ohms): 1; Power (Watts): 0.063W, 1/16W; .Checked PCB: used; Description: RES 1.00 OHM 1/16W 1% 0402 SMD; Temperature Coefficient: ±200ppm/°C
R123 = RC0402FR-0739KL: RES 39.0K OHM 1/16W 1% 0402 SMD; Manufacturer: Yageo; Power (Watts): 0.063W, 1/16W; .Checked PCB: used; Temperature Coefficient: ±100ppm/°C
R124 R125 = RC0402FR-07200KL: RES 200K OHM 1/16W 1% 0402 SMD; Manufacturer: Yageo; Power (Watts): 0.063W, 1/16W; .Checked PCB: used; Temperature Coefficient: ±100ppm/°C
R126 = CRCW040210K5FKED: RES 10.5K OHM 1/16W 1% 0402 SMD; Manufacturer: Vishay/Dale; Power (Watts): 0.063W, 1/16W; .Checked PCB: used; Temperature Coefficient: ±100ppm/°C
R127 R129-R133 R136 = RC0402FR-0710KL: as R75 on sheet [13] - ETHERNET PHY
R138 = CRCW0402330KFKED: RES 330K OHM 1/16W 1% 0402 SMD; Manufacturer: Vishay Dale; Power (Watts): 0.063W, 1/16W; Temperature Coefficient: ±100ppm/°C; .Checked PCB: RF
R139 = RC0402FR-07120KL: RES 120K OHM 1/16W 1% 0402 SMD; Manufacturer: Yageo; Power (Watts): 0.063W, 1/16W; .Checked PCB: OK RF; .Checked SCH: RF; Temperature Coefficient: ±100ppm/°C
TP6 TP7 TP11 = TP_25MILC: Test Point 25mil
U11 = ISL6236AIRZ: IC MAIN PWR CTRLR QUAD 32-QFN; Manufacturer: Intersil; .Checked PCB: used; Voltage - Input: 4.5 V ~ 25 V; Number of Outputs: 4; Voltage - Output: Multiple
U12 = TPS62175DQCT: IC REG BUCK SYNC ADJ 0.5A 10WSON; Manufacturer: Texas Instruments; Output Type: Adjustable; Number of Outputs: 1; Voltage - Output: 1 V ~ 6 V; Voltage - Input: 4.75 V ~ 28 V; PWM Type: Hybrid; Frequency - Switching: 1MHz; Current - Output: 500mA; Synchronous Rectifier: Yes; .Creator: MM; .Checked PCB: MM, checked by RF

## Sheet [16] - PWR 2V5, 1V5.SchDoc
size A2; DocumentNumber: 16; SheetNumber: 16; SheetTotal: 20
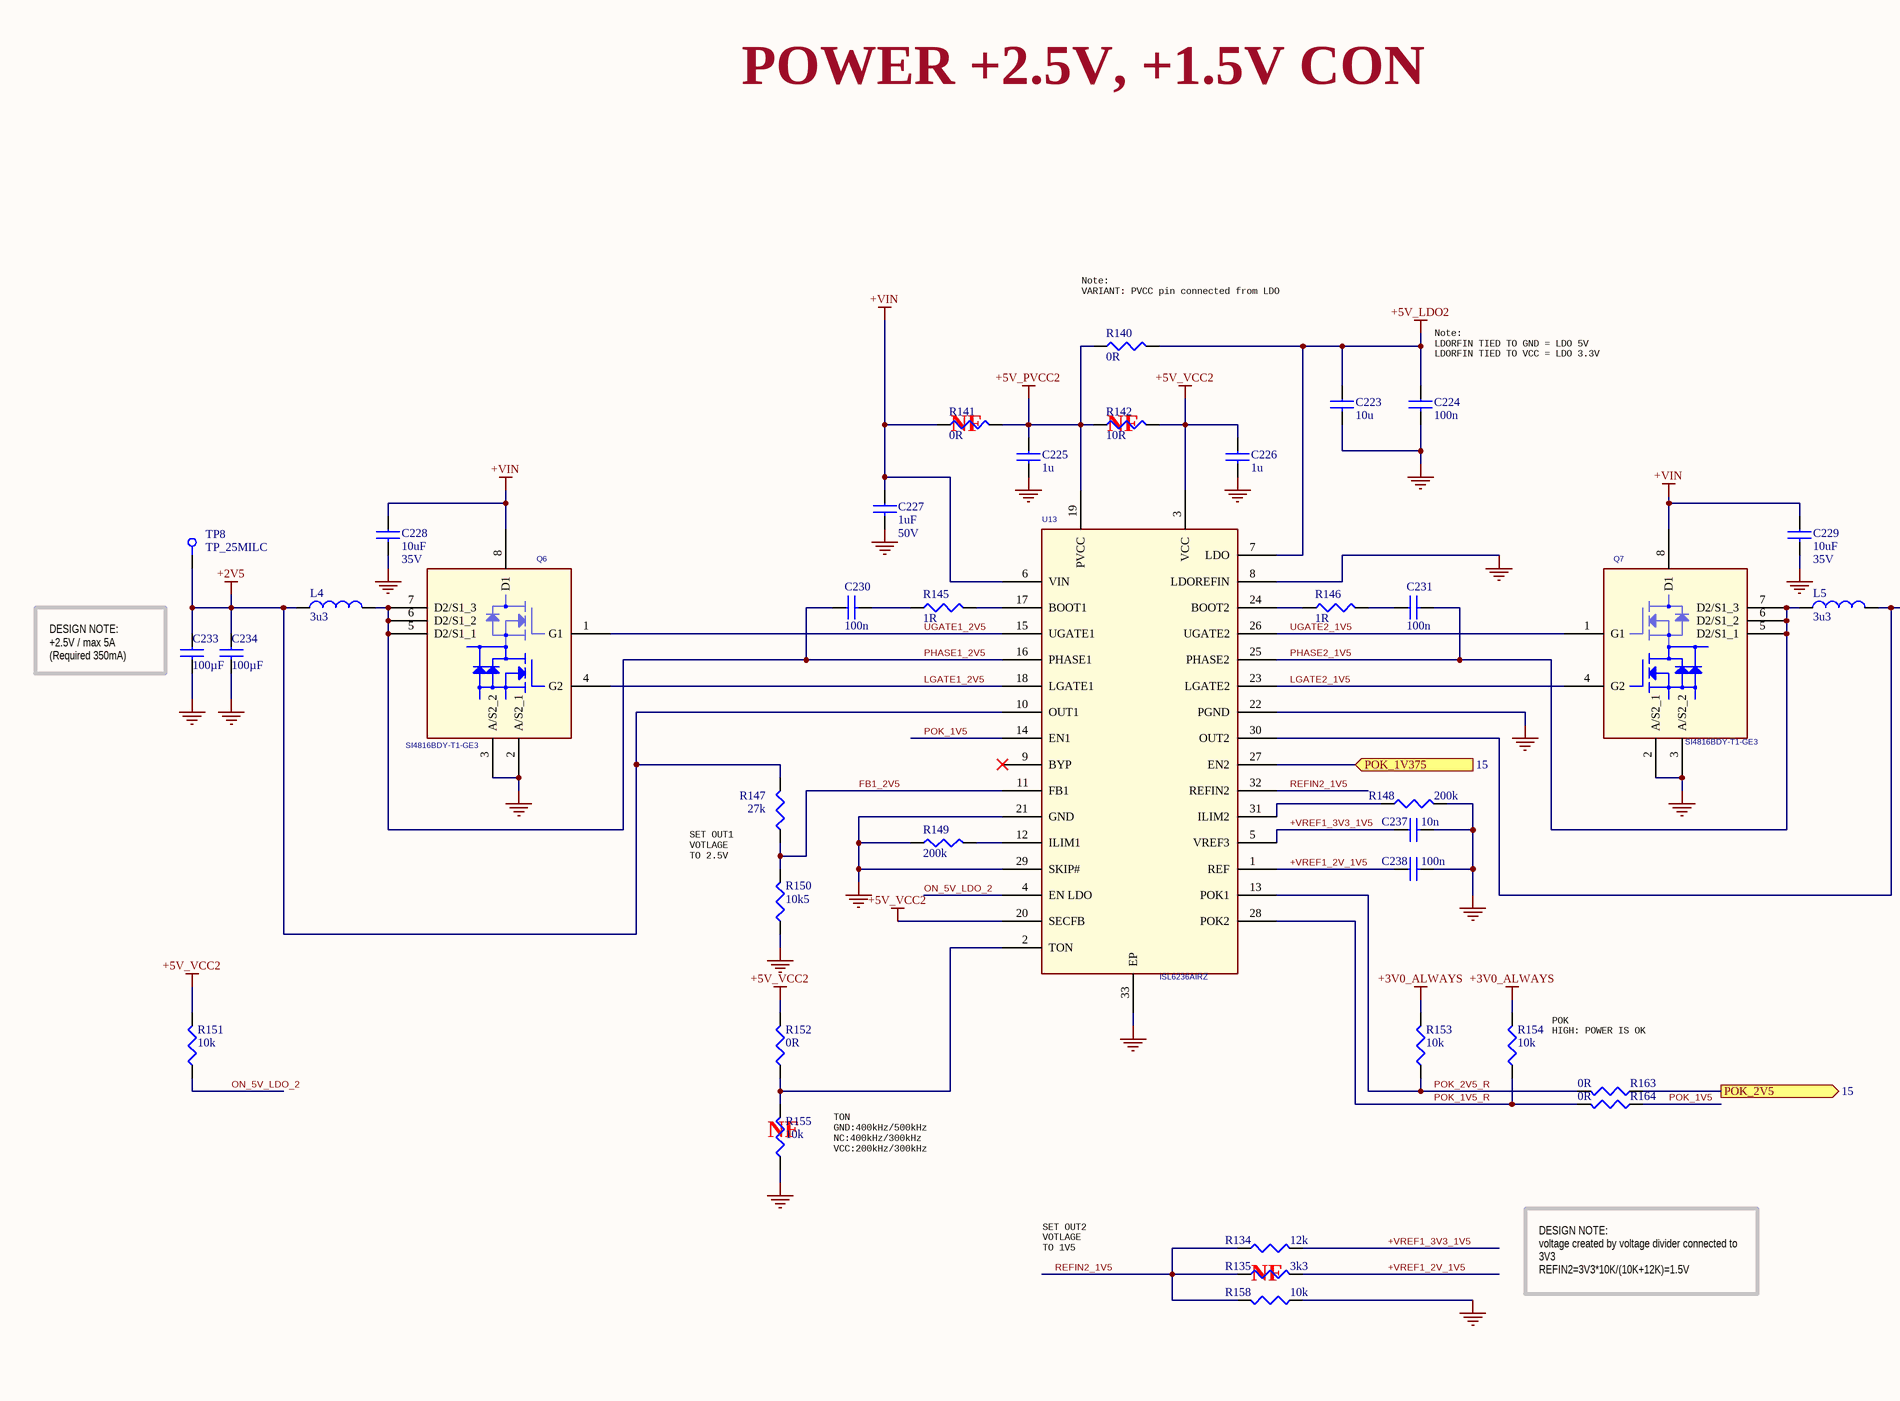
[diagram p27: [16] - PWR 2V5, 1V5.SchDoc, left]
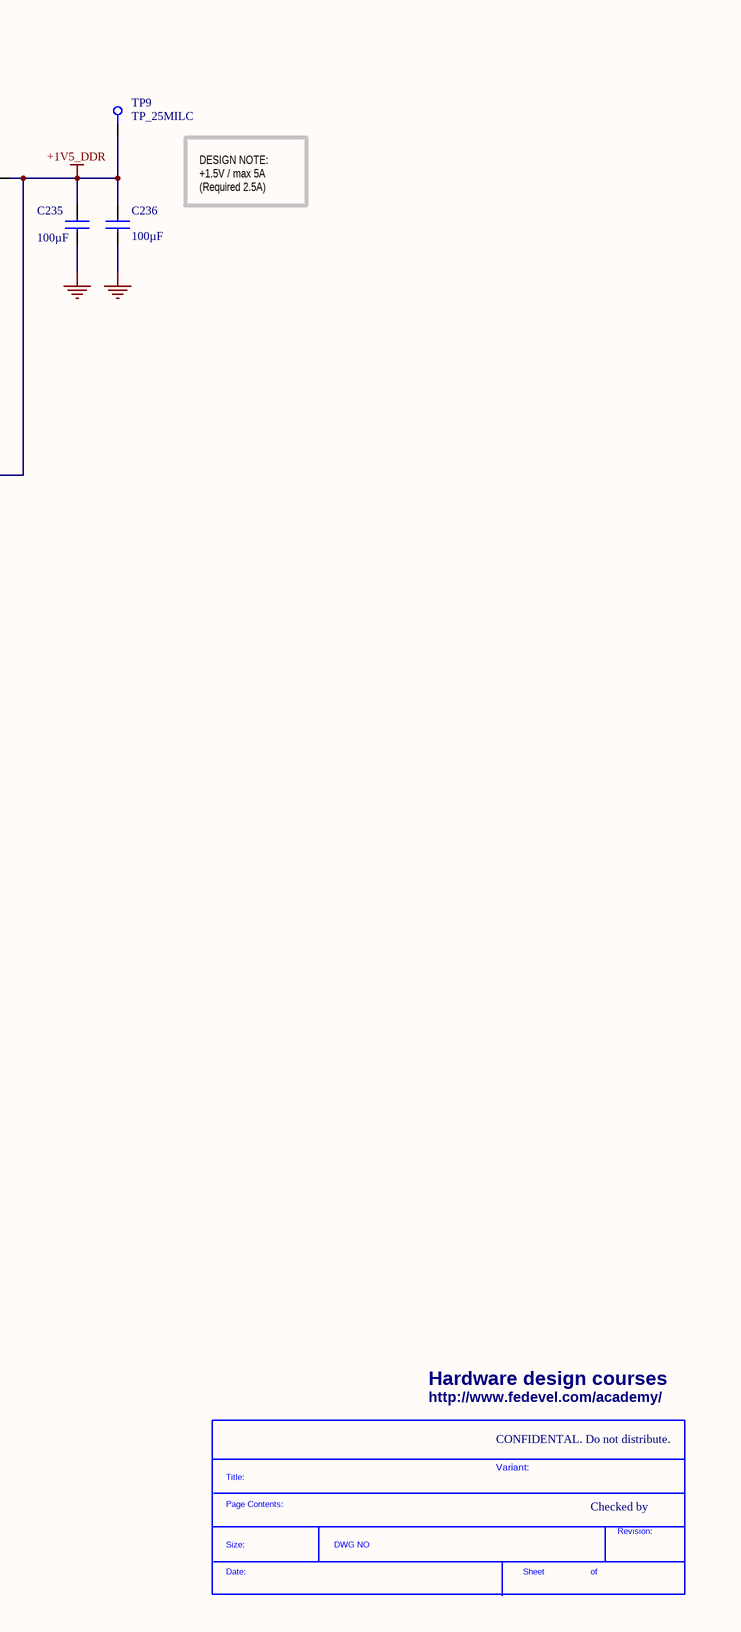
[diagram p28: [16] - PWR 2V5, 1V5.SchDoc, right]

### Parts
(Parts that share a designator on the sheet are numbered #1, #2 ... from top to bottom, then left to right.)
*#18  SDTitleBlock  (value not drawn)  (graphical)
C223  10u  [C0603]
C224  100n  [C0402]
C225  1u  [C0402]
C226  1u  [C0402]
C227  1uF  Voltage - Rated: 50V  [C0805]
C228  10uF  Voltage - Rated: 35V  [C1206]
C229  10uF  Voltage - Rated: 35V  [C1206]
C230  100n  [C0402]
C231  100n  [C0402]
C233  100µF  [C1206]
C234  100µF  [C1206]
C235  100µF  [C1206]
C236  100µF  [C1206]
C237  10n  [C0402]
C238  100n  [C0402]
L4  3u3  [IHLP_255MILx270MIL]
L5  3u3  [IHLP_255MILx270MIL]
Q6  SI4816BDY-T1-GE3  [8_SOIC_3.9MM]
Q7  SI4816BDY-T1-GE3  [8_SOIC_3.9MM]
R134  12k  [R0402]
R135  3k3  [R0402]
R140  0R  [R0402]
R141  0R  [R0402]
R142  10R  [R0402]
R145  1R  [R0402]
R146  1R  [R0402]
R147  27k  [R0402]
R148  200k  [R0402]
R149  200k  [R0402]
R150  10k5  [R0402]
R151  10k  [R0402]
R152  0R  [R0402]
R153  10k  [R0402]
R154  10k  [R0402]
R155  10k  [R0402]
R158  10k  [R0402]
R163  0R  [R0402]
R164  0R  [R0402]
TP8  TP_25MILC  [TP_25C]  (no BOM)
TP9  TP_25MILC  [TP_25C]  (no BOM)
U13  ISL6236AIRZ  [32_VFQFN_EXPOSED_PAD]

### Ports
POK_1V375 (in, see 15), POK_2V5 (out, see 15)

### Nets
+1V5_DDR: C235.1 C236.1 L5.2 TP9.1 U13.30(OUT2)
+2V5: C233.1 C234.1 L4.1 R147.2 TP8.1 U13.10(OUT1)
+3V0_ALWAYS: R153.2 R154.2
+5V_LDO2: C223.1 C224.1 R140.2 U13.7(LDO)
+5V_PVCC2: C225.1 R140.1 R141.2 R142.1 U13.19(PVCC)
+5V_VCC2: C226.1 R142.2 R151.2 R152.2 U13.3(VCC) U13.20(SECFB)
+VIN: C227.1 C228.1 C229.1 Q6.8(D1) Q7.8(D1) R141.1 U13.6(VIN)
GND: C223.2 C224.2 C225.2 C226.2 C227.2 C228.2 C229.2 C233.2 C234.2 C235.2 C236.2 C237.2 C238.2 Q6.2(A/S2_1) Q6.3(A/S2_2) Q7.2(A/S2_1) Q7.3(A/S2_2) R148.2 R149.1 R150.1 R155.1 R158.1 U13.8(LDOREFIN) U13.21(GND) U13.22(PGND) U13.29(SKIP#) U13.33(EP)
+VREF1_2V_1V5: C238.1 R135.2 U13.1(REF)
+VREF1_3V3_1V5: C237.1 R134.2 U13.5(VREF3)
FB1_2V5: R147.1 R150.2 U13.11(FB1)
LGATE1_2V5: Q6.4(G2) U13.18(LGATE1)
LGATE2_1V5: Q7.4(G2) U13.23(LGATE2)
ON_5V_LDO_2: R151.1 U13.4(EN_LDO)
PHASE1_2V5: C230.1 L4.2 Q6.5(D2/S1_1) Q6.6(D2/S1_2) Q6.7(D2/S1_3) U13.16(PHASE1)
PHASE2_1V5: C231.2 L5.1 Q7.5(D2/S1_1) Q7.6(D2/S1_2) Q7.7(D2/S1_3) U13.25(PHASE2)
POK_1V5: R164.1 U13.14(EN1)
POK_1V5_R: R154.1 R164.2 U13.28(POK2)
POK_1V375: U13.27(EN2) ; port POK_1V375
POK_2V5: R163.1 ; port POK_2V5
POK_2V5_R: R153.1 R163.2 U13.13(POK1)
REFIN2_1V5: R134.1 R135.1 R158.2 U13.32(REFIN2)
UGATE1_2V5: Q6.1(G1) U13.15(UGATE1)
UGATE2_1V5: Q7.1(G1) U13.26(UGATE2)
NetC230_2: C230.2 R145.1
NetC231_1: C231.1 R146.2
NetR145_2: R145.2 U13.17(BOOT1)
NetR146_1: R146.1 U13.24(BOOT2)
NetR148_1: R148.1 U13.31(ILIM2)
NetR149_2: R149.2 U13.12(ILIM1)
NetR152_1: R152.1 R155.2 U13.2(TON)

Not connected (* = marked no-connect by the designer): U13 9(BYP)*

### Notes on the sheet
- POWER +2.5V, +1.5V CON
- (near R140) Note:
  VARIANT: PVCC pin connected from LDO
- (near C224) Note:
  LDORFIN TIED TO GND = LDO 5V
  LDORFIN TIED TO VCC = LDO 3.3V
- (near R141) NF
- (near R142) NF
- (near C233) DESIGN NOTE:
  +2.5V / max 5A
  (Required 350mA)
- DESIGN NOTE:
  +1.5V / max 5A
  (Required 2.5A)
- SET OUT1
  VOTLAGE
  TO 2.5V
- POK
  HIGH: POWER IS OK
- (near R155) NF
- TON
  GND:400kHz/500kHz
  NC:400kHz/300kHz
  VCC:200kHz/300kHz
- SET OUT2
  VOTLAGE
  TO 1V5
- (near R135) NF
- DESIGN NOTE:
  voltage created by voltage divider connected to 3V3
  REFIN2=3V3*10K/(10K+12K)=1.5V
- Hardware design courses
- http://www.fedevel.com/academy/
- CONFIDENTAL. Do not distribute.
- Variant:
- Checked by

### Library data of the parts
C223 = C1608X5R0J106M: as C177 on sheet [13] - ETHERNET PHY
C224 C230 C231 C238 = C1005X5R1H104K: as C181 on sheet [13] - ETHERNET PHY
C225 C226 = C1005X5R1C105K: as C206 on sheet [15] - PWR 3V3, 1V375
C227 = GRM21BR71H105KA12L: as C208 on sheet [15] - PWR 3V3, 1V375
C228 C229 = GRM31CR6YA106KA12L: as C209 on sheet [15] - PWR 3V3, 1V375
C233-C236 = C3216X5R1A107M: as C213 on sheet [15] - PWR 3V3, 1V375
C237 = C1005X7R1C103K: as C182 on sheet [13] - ETHERNET PHY
L4 L5 = IHLP2525CZER3R3M01: as L2 on sheet [15] - PWR 3V3, 1V375
Q6 Q7 = SI4816BDY-T1-GE3: as Q3 on sheet [15] - PWR 3V3, 1V375
R134 = RC0402FR-0712KL: RES 12.0K OHM 1/16W 1% 0402 SMD; Manufacturer: Yageo; Power (Watts): 0.063W, 1/16W; .Checked PCB: used; Temperature Coefficient: ±100ppm/°C
R135 = RC0402FR-073K3L: RES 3.30K OHM 1/16W 1% 0402 SMD; Manufacturer: Yageo; Resistance (Ohms): 3.3K; Power (Watts): 0.063W, 1/16W; .Checked PCB: used; Temperature Coefficient: ±100ppm/°C
R140 R141 R152 R163 R164 = RC0402JR-070RL: as R93 on sheet [15] - PWR 3V3, 1V375
R142 = RC0402FR-0710RL: as R118 on sheet [15] - PWR 3V3, 1V375
R145 R146 = RC0402FR-071RL: as R121 on sheet [15] - PWR 3V3, 1V375
R147 = RC0402FR-0727KL: RES 27.0K OHM 1/16W 1% 0402 SMD; Manufacturer: Yageo; Power (Watts): 0.063W, 1/16W; .Checked PCB: RF; Temperature Coefficient: ±100ppm/°C
R148 R149 = RC0402FR-07200KL: as R124 on sheet [15] - PWR 3V3, 1V375
R150 = CRCW040210K5FKED: as R126 on sheet [15] - PWR 3V3, 1V375
R151 R153-R155 R158 = RC0402FR-0710KL: as R75 on sheet [13] - ETHERNET PHY
TP8 TP9 = TP_25MILC: Test Point 25mil
U13 = ISL6236AIRZ: as U11 on sheet [15] - PWR 3V3, 1V375

## Sheet [17] - MECH.SchDoc
size A2; DocumentNumber: 17; SheetNumber: 17; SheetTotal: 20
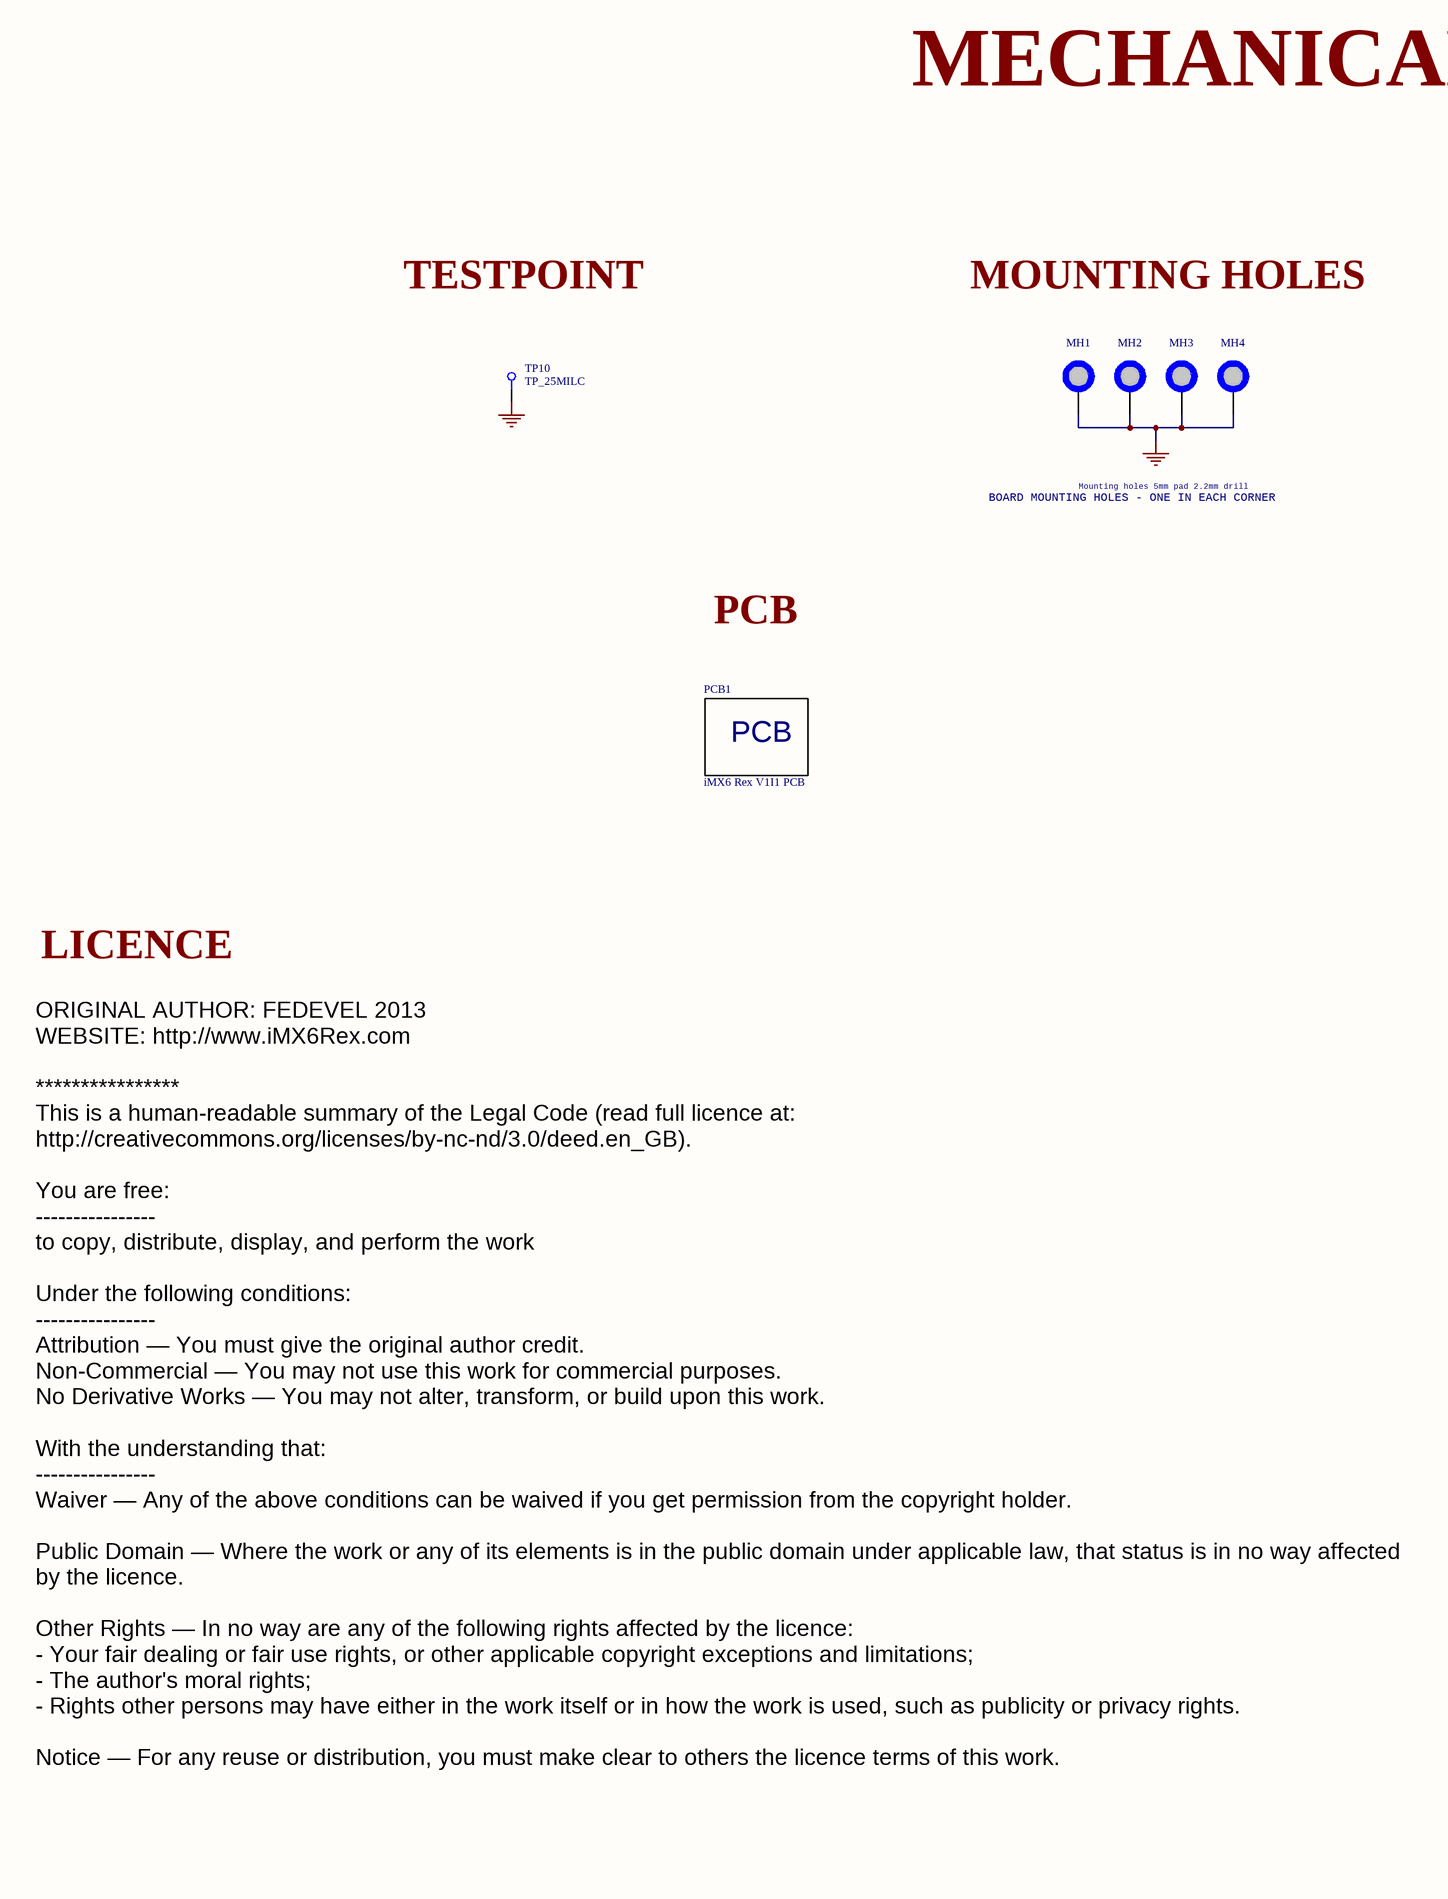
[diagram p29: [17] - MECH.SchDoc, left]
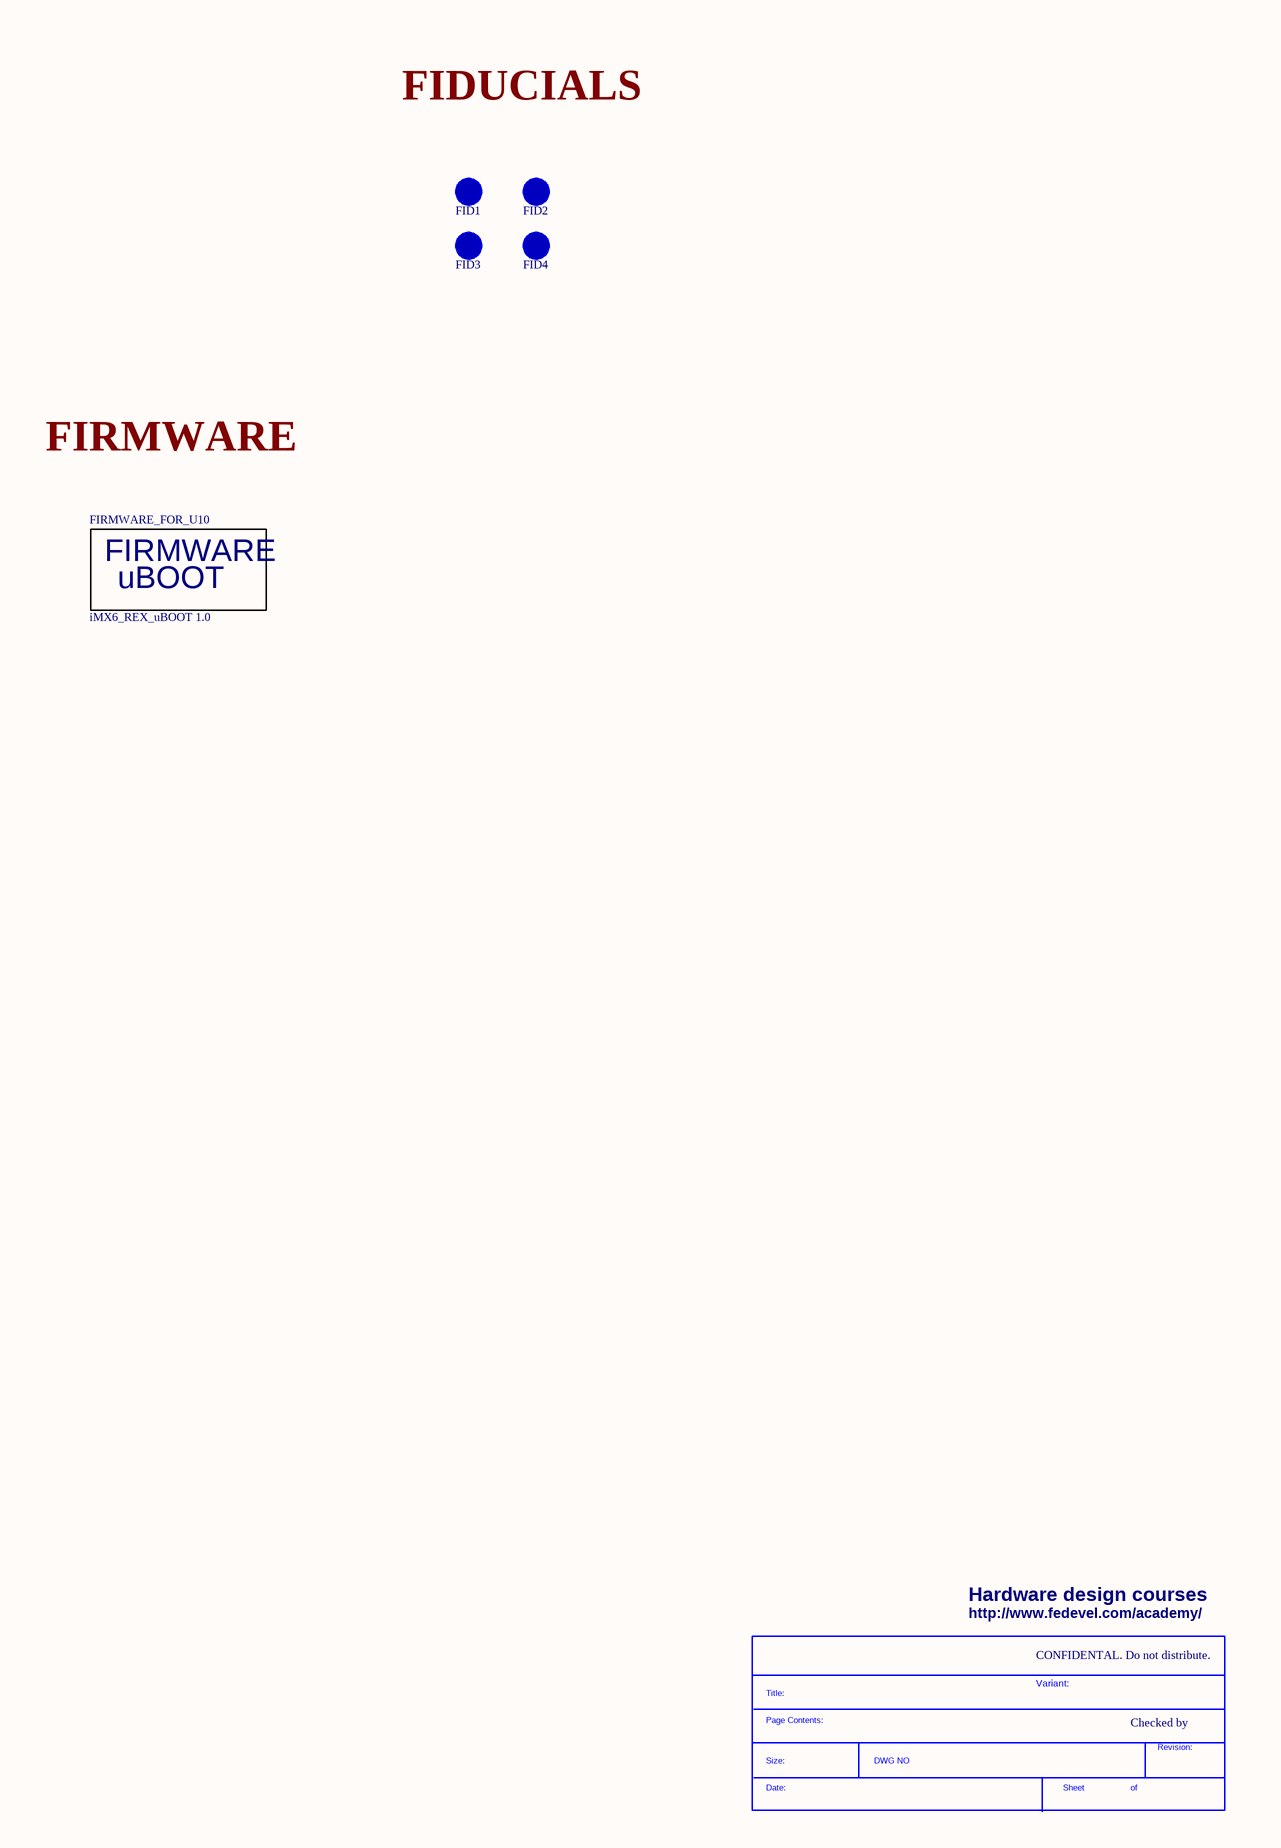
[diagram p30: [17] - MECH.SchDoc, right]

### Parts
(Parts that share a designator on the sheet are numbered #1, #2 ... from top to bottom, then left to right.)
*#19  SDTitleBlock  (value not drawn)  (graphical)
FID1  FID_1MM_SMALL  [FID_40X52D]  (value not drawn)  (no BOM)
FID2  FID_1MM_SMALL  [FID_40X52D]  (value not drawn)  (no BOM)
FID3  FID_1MM_SMALL  [FID_40X52D]  (value not drawn)  (no BOM)
FID4  FID_1MM_SMALL  [FID_40X52D]  (value not drawn)  (no BOM)
FIRMWARE_FOR_U10  iMX6_REX_uBOOT 1.0  (mechanical)
MH1  MH_5MMC_2.2MMD  [MH_5MMD_2.2MMD]  (value not drawn)  (no BOM)
MH2  MH_5MMC_2.2MMD  [MH_5MMD_2.2MMD]  (value not drawn)  (no BOM)
MH3  MH_5MMC_2.2MMD  [MH_5MMD_2.2MMD]  (value not drawn)  (no BOM)
MH4  MH_5MMC_2.2MMD  [MH_5MMD_2.2MMD]  (value not drawn)  (no BOM)
PCB1  iMX6 Rex V1I1 PCB  (mechanical)
TP10  TP_25MILC  [TP_25C]  (no BOM)

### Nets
GND: MH1.1 MH2.1 MH3.1 MH4.1 TP10.1

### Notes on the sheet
- MECHANICAL
- TESTPOINT
- MOUNTING HOLES
- FIDUCIALS
- BOARD MOUNTING HOLES - ONE IN EACH CORNER
- Mounting holes 5mm pad 2.2mm drill
- PCB
- FIRMWARE
- LICENCE
- Hardware design courses
- http://www.fedevel.com/academy/
- CONFIDENTAL. Do not distribute.
- ORIGINAL AUTHOR: FEDEVEL 2013
  WEBSITE: http://www.iMX6Rex.com
  ****************
  This is a human-readable summary of the Legal Code (read full licence at:
  http://creativecommons.org/licenses/by-nc-nd/3.0/deed.en_GB).
  You are free:
  ----------------
  to copy, distribute, display, and perform the work
  Under the following conditions:
  ----------------
  Attribution — You must give the original author credit.
  Non-Commercial — You may not use this work for commercial purposes.
  No Derivative Works — You may not alter, transform, or build upon this work.
  With the understanding that:
  ----------------
  Waiver — Any of the above conditions can be waived if you get permission from the copyright holder.
  Public Domain — Where the work or any of its elements is in the public domain under applicable law, that status is in no way affected by the licence.
  Other Rights — In no way are any of the following rights affected by the licence:
  - Your fair dealing or fair use rights, or other applicable copyright exceptions and limitations;
  - The author's moral rights;
  - Rights other persons may have either in the work itself or in how the work is used, such as publicity or privacy rights.
  Notice — For any reuse or distribution, you must make clear to others the licence terms of this work.
- Variant:
- Checked by

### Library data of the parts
FID1-FID4 = FID_1MM_SMALL: Fiducial 40mil Diameter, 52mil Mask
FIRMWARE_FOR_U10 = FIRMWARE_iMX6_Rex_uBOOT 1.0: .Creator: MM
MH1-MH4 = MH_5MMC_2.2MMD: Mounting Hole 5mm Diameter, 2.2mm Drill
PCB1 = PCB_iMX6_REX_V1I1: Printed Circuit Board; .Creator: MM
TP10 = TP_25MILC: Test Point 25mil

## Sheet [18] - POWER SEQUENCING.SchDoc
size A2; DocumentNumber: 18; SheetNumber: 18; SheetTotal: 20
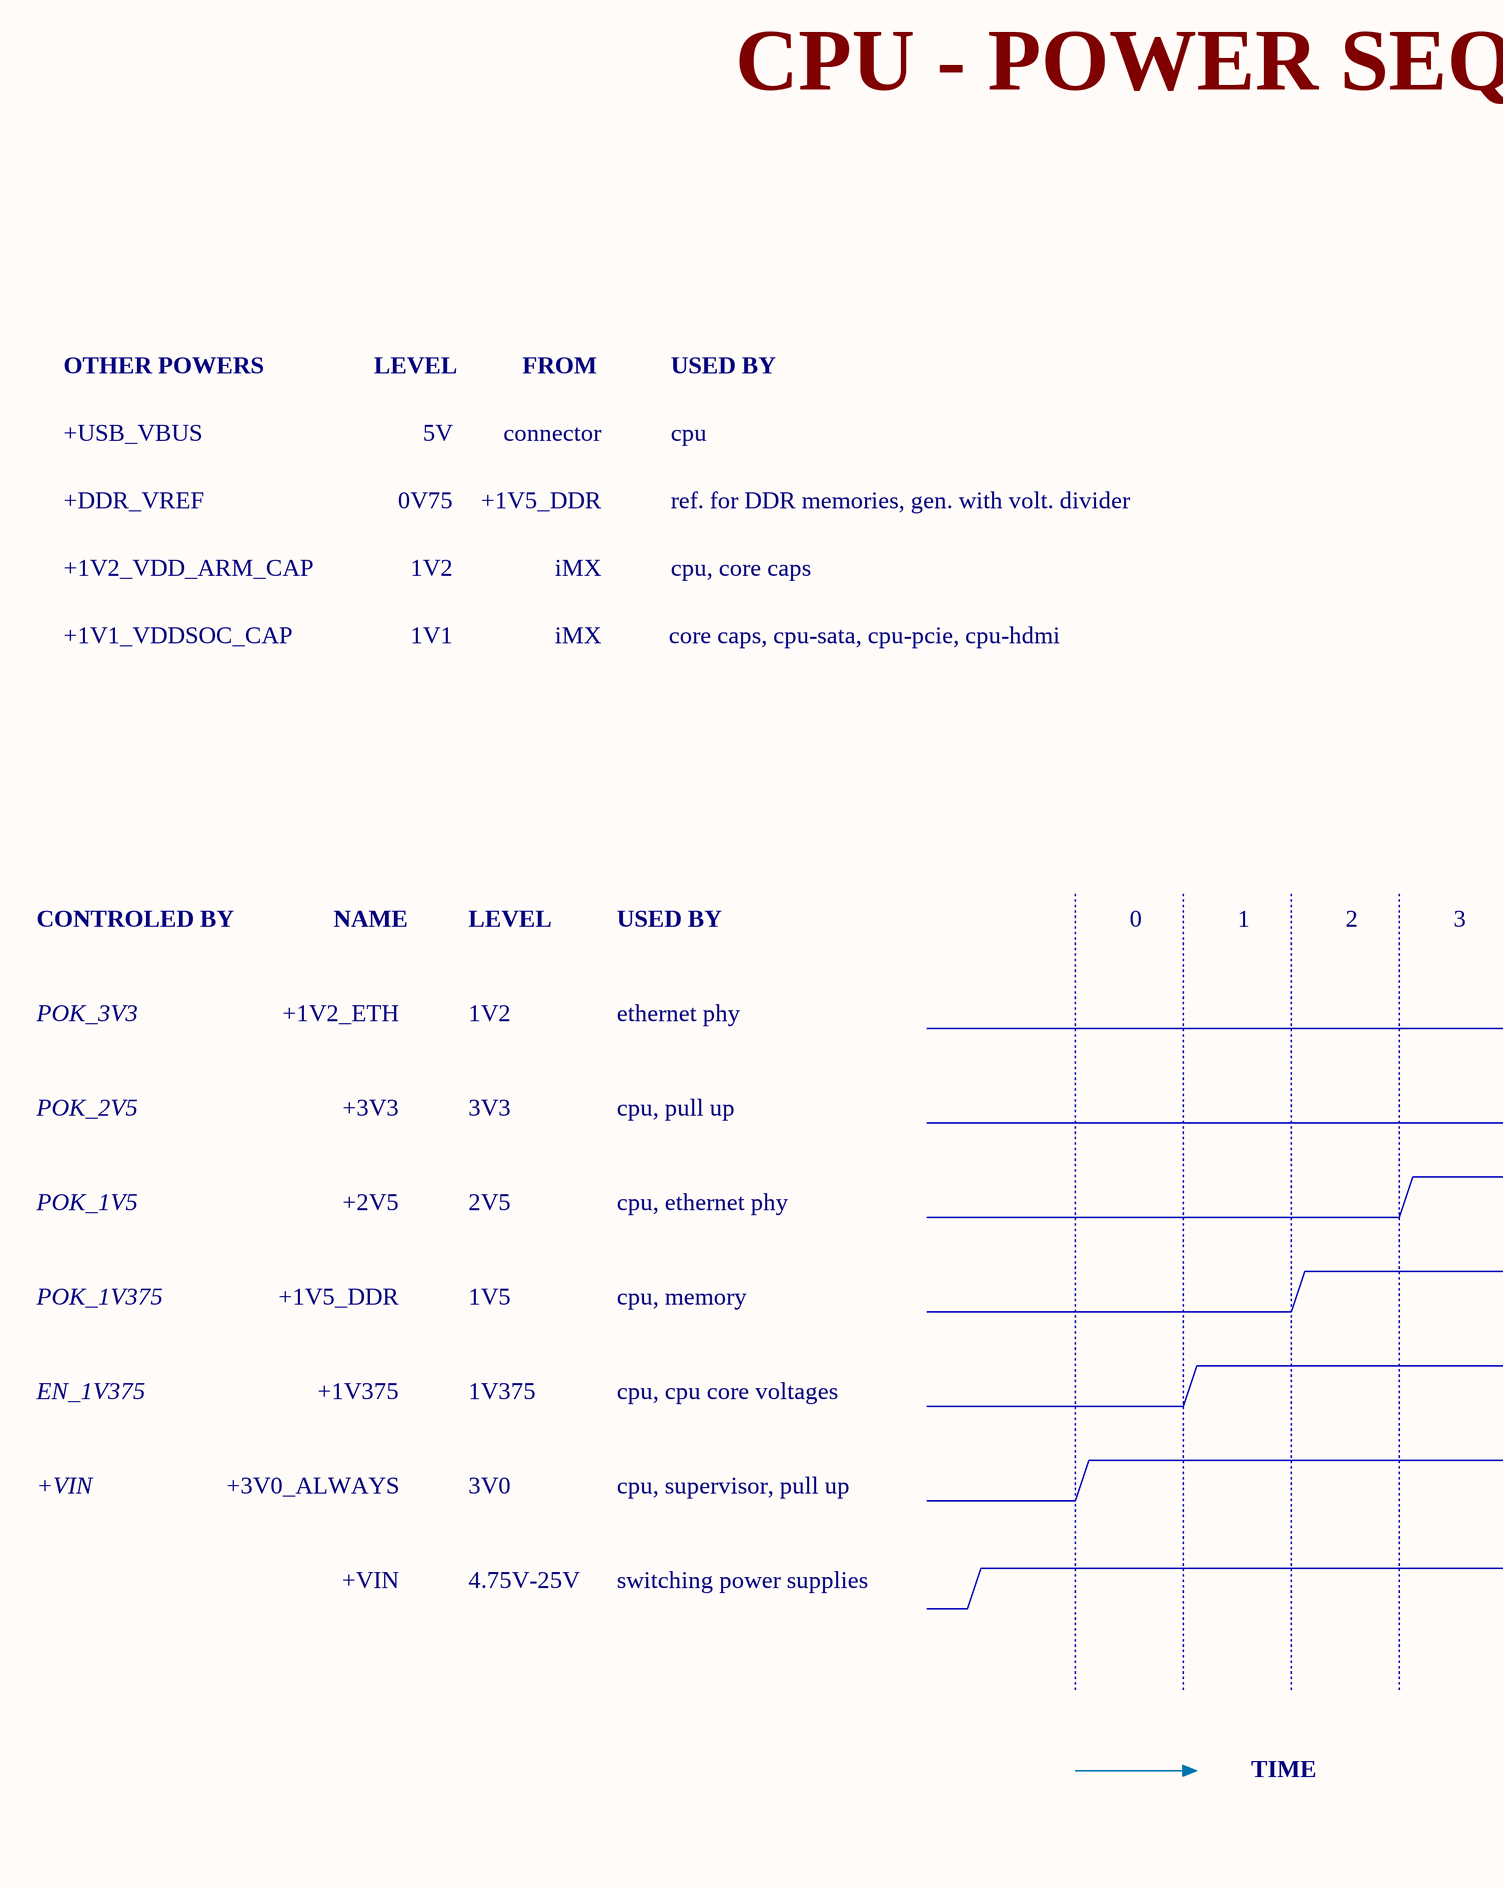
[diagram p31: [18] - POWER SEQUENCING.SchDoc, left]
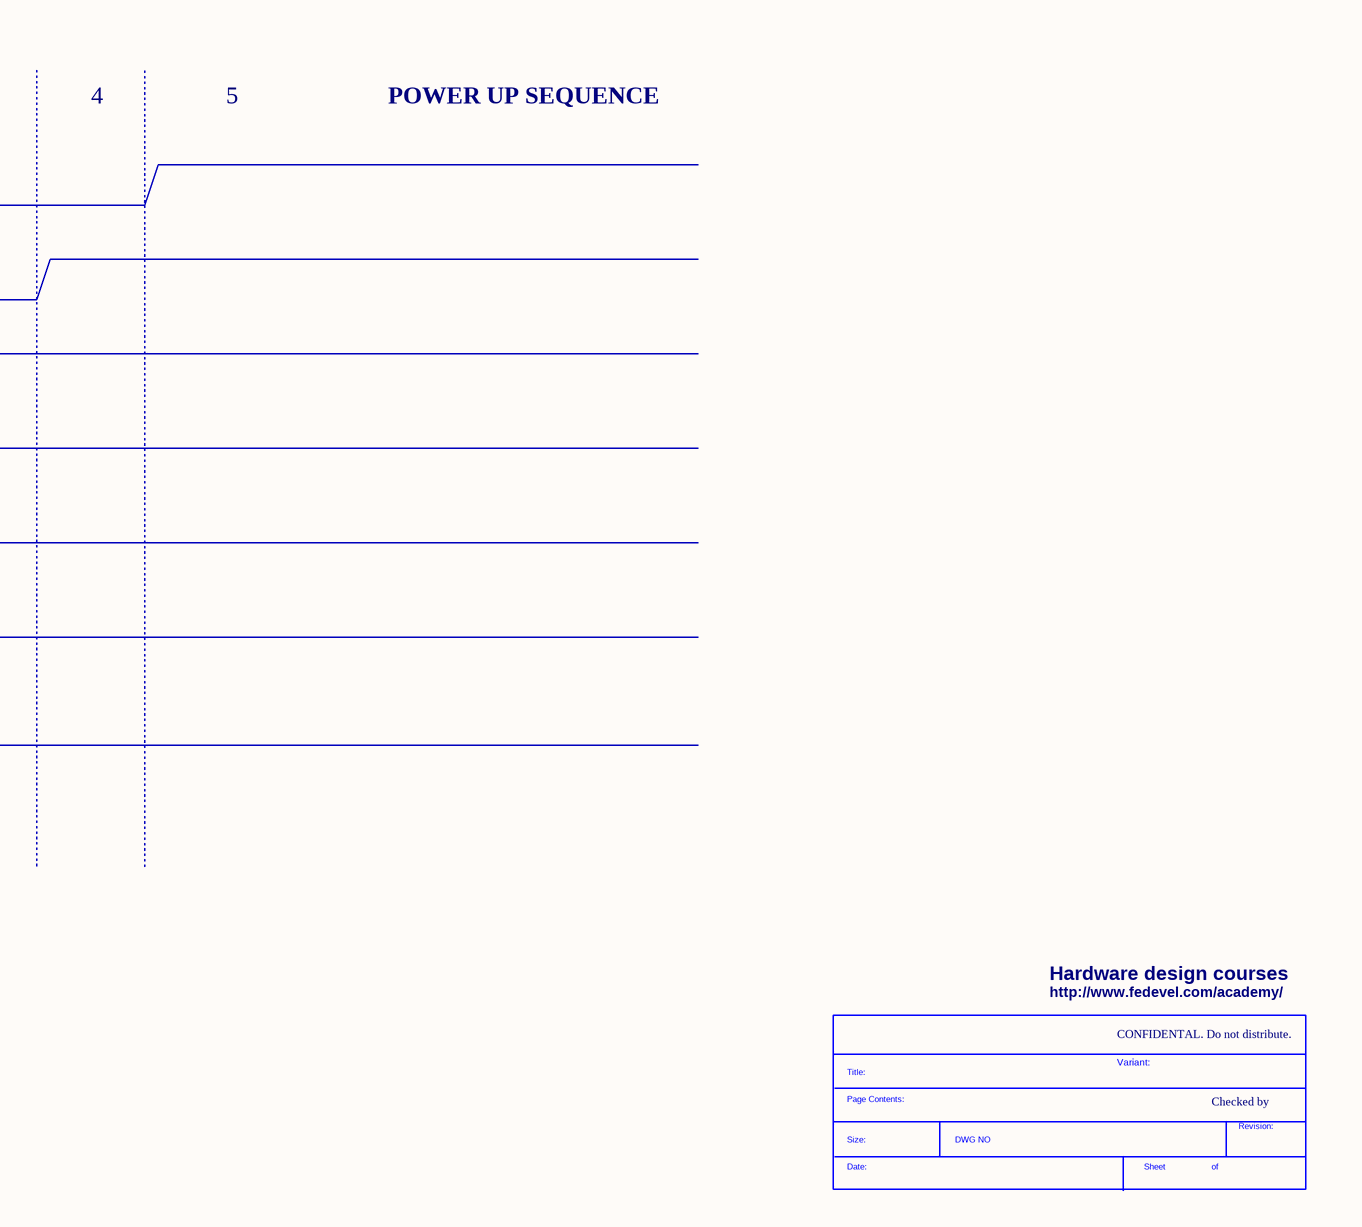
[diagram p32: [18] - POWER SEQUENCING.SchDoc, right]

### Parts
(Parts that share a designator on the sheet are numbered #1, #2 ... from top to bottom, then left to right.)
*#20  SDTitleBlock  (value not drawn)  (graphical)

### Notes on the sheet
- CPU - POWER SEQUENCING
- OTHER POWERS
- LEVEL
- FROM
- USED BY
- +USB_VBUS
- 5V
- connector
- cpu
- +DDR_VREF
- 0V75
- +1V5_DDR
- ref. for DDR memories, gen. with volt. divider
- +1V2_VDD_ARM_CAP
- 1V2
- iMX
- cpu, core caps
- +1V1_VDDSOC_CAP
- 1V1
- core caps, cpu-sata, cpu-pcie, cpu-hdmi
- CONTROLED BY
- NAME
- 0
- 1
- 2
- 3
- 4
- 5
- POWER UP SEQUENCE
- POK_3V3
- +1V2_ETH
- ethernet phy
- POK_2V5
- +3V3
- 3V3
- cpu, pull up
- POK_1V5
- +2V5
- 2V5
- cpu, ethernet phy
- POK_1V375
- 1V5
- cpu, memory
- EN_1V375
- +1V375
- 1V375
- cpu, cpu core voltages
- +VIN
- +3V0_ALWAYS
- 3V0
- cpu, supervisor, pull up
- 4.75V-25V
- switching power supplies
- TIME
- Hardware design courses
- http://www.fedevel.com/academy/
- CONFIDENTAL. Do not distribute.
- Variant:
- Checked by

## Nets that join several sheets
+1V1_VDDSOC_CAP: [05] - CPU - PCIE, SATA (C78.1 FB1.1 R13.1 R18.1), [06] - CPU - HDMI, LVDS (C246.1 R23.1), [11] - CPU - POWER (16 pins)
+1V2_ETH: [11] - CPU - POWER (R105.2), [13] - ETHERNET PHY (11 pins)
+1V5_DDR: [04] - CPU - DDR3, DDR3 MEM (134 pins), [10] - CPU - JTAG, CONTROL (R59.2), [11] - CPU - POWER (13 pins), [16] - PWR 2V5, 1V5 (5 pins)
+1V375: [11] - CPU - POWER (30 pins), [13] - ETHERNET PHY (FB8.2), [15] - PWR 3V3, 1V375 (6 pins)
+2V5: [05] - CPU - PCIE, SATA (C244.1 C245.1 R14.1 R19.1), [06] - CPU - HDMI, LVDS (C247.1 R27.1 R34.1), [11] - CPU - POWER (C153.1 R74.2 R78.2 R80.2), [13] - ETHERNET PHY (FB6.1), [16] - PWR 2V5, 1V5 (6 pins)
+3V0_ALWAYS: [10] - CPU - JTAG, CONTROL (9 pins), [11] - CPU - POWER (6 pins), [15] - PWR 3V3, 1V375 (8 pins), [16] - PWR 2V5, 1V5 (R153.2 R154.2)
+3V3: [06] - CPU - HDMI, LVDS (7 pins), [07] - CPU - USB, ETHERNET (R100.2), [09] - CPU - UART, AUDIO (R46.2 R47.2), [08] - CPU - SPI, I2C, SD, MMC (8 pins), [03] - CONNECTORS (C1.1 J2.50), [10] - CPU - JTAG, CONTROL (10 pins), [11] - CPU - POWER (21 pins), [13] - ETHERNET PHY (C177.1 FB7.1 U9.1), [14] - SPI FLASH, LEDS (7 pins), [15] - PWR 3V3, 1V375 (8 pins)
+5V_USB_VBUS: [07] - CPU - USB, ETHERNET (C79.1 C82.1 U1.D10 U1.E9), [03] - CONNECTORS (C242.1 J1.18)
+VIN: [03] - CONNECTORS (9 pins), [15] - PWR 3V3, 1V375 (10 pins), [16] - PWR 2V5, 1V5 (7 pins)
GND: [04] - CPU - DDR3, DDR3 MEM (149 pins), [05] - CPU - PCIE, SATA (12 pins), [06] - CPU - HDMI, LVDS (9 pins), [07] - CPU - USB, ETHERNET (C79.2 C80.2 C81.2 C82.2), [03] - CONNECTORS (16 pins), [10] - CPU - JTAG, CONTROL (18 pins), [11] - CPU - POWER (195 pins), [13] - ETHERNET PHY (39 pins), [14] - SPI FLASH, LEDS (5 pins), [15] - PWR 3V3, 1V375 (39 pins), [16] - PWR 2V5, 1V5 (27 pins), [17] - MECH (5 pins)
AUD3_CLK: [09] - CPU - UART, AUDIO (R160.2), [03] - CONNECTORS (J2.20)
AUD3_RXD: [09] - CPU - UART, AUDIO (U1.N3), [03] - CONNECTORS (J2.22)
AUD3_TXC: [09] - CPU - UART, AUDIO (R72.2), [03] - CONNECTORS (J2.16)
AUD3_TXD: [09] - CPU - UART, AUDIO (U1.P2), [03] - CONNECTORS (J2.18)
AUD3_TXFS: [09] - CPU - UART, AUDIO (U1.N4), [03] - CONNECTORS (J2.24)
BOOT_MODE: [03] - CONNECTORS (J1.50), [10] - CPU - JTAG, CONTROL (Q9.1 R165.1)
CLK1_N: [05] - CPU - PCIE, SATA (C66.2 R17.2), [03] - CONNECTORS (J2.46)
CLK1_P: [05] - CPU - PCIE, SATA (C67.2 R16.2), [03] - CONNECTORS (J2.48)
CPU_GPIO0: [08] - CPU - SPI, I2C, SD, MMC (R45.1 R157.1 U1.E15), [03] - CONNECTORS (J1.35)
CPU_GPIO1: [08] - CPU - SPI, I2C, SD, MMC (R44.1 R156.1 U1.D16), [03] - CONNECTORS (J1.37)
CSPI2_CLK: [08] - CPU - SPI, I2C, SD, MMC (R159.2), [03] - CONNECTORS (J1.17)
CSPI2_CS0: [08] - CPU - SPI, I2C, SD, MMC (U1.V25), [03] - CONNECTORS (J1.19)
CSPI2_MISO: [08] - CPU - SPI, I2C, SD, MMC (U1.U24), [03] - CONNECTORS (J1.21)
CSPI2_MOSI: [08] - CPU - SPI, I2C, SD, MMC (U1.T21), [03] - CONNECTORS (J1.23)
CSPI3_CLK: [08] - CPU - SPI, I2C, SD, MMC (R112.2), [14] - SPI FLASH, LEDS (U10.6)
CSPI3_CS2: [08] - CPU - SPI, I2C, SD, MMC (U1.R25), [14] - SPI FLASH, LEDS (U10.1)
CSPI3_MISO: [08] - CPU - SPI, I2C, SD, MMC (U1.P23), [14] - SPI FLASH, LEDS (U10.2)
CSPI3_MOSI: [08] - CPU - SPI, I2C, SD, MMC (U1.P22), [14] - SPI FLASH, LEDS (U10.5)
ENET_LED_LINK: [03] - CONNECTORS (J1.56), [13] - ETHERNET PHY (R81.2)
ENET_LED_RX: [03] - CONNECTORS (J1.55), [13] - ETHERNET PHY (R82.2)
ENET_REF_CLK: [07] - CPU - USB, ETHERNET (U1.V22), [13] - ETHERNET PHY (R36.2)
HDMI_CEC_IN: [06] - CPU - HDMI, LVDS (R22.1 R24.2 R25.2), [03] - CONNECTORS (J1.44)
HDMI_CLK_N: [06] - CPU - HDMI, LVDS (U1.J5), [03] - CONNECTORS (J1.45)
HDMI_CLK_P: [06] - CPU - HDMI, LVDS (U1.J6), [03] - CONNECTORS (J1.47)
HDMI_D0_N: [06] - CPU - HDMI, LVDS (U1.K5), [03] - CONNECTORS (J1.39)
HDMI_D0_P: [06] - CPU - HDMI, LVDS (U1.K6), [03] - CONNECTORS (J1.41)
HDMI_D1_N: [06] - CPU - HDMI, LVDS (U1.J3), [03] - CONNECTORS (J1.46)
HDMI_D1_P: [06] - CPU - HDMI, LVDS (U1.J4), [03] - CONNECTORS (J1.48)
HDMI_D2_N: [06] - CPU - HDMI, LVDS (U1.K3), [03] - CONNECTORS (J1.40)
HDMI_D2_P: [06] - CPU - HDMI, LVDS (U1.K4), [03] - CONNECTORS (J1.42)
HDMI_HPD: [06] - CPU - HDMI, LVDS (C74.2 R21.1 U1.K1), [03] - CONNECTORS (J1.43)
I2C1_SCL: [09] - CPU - UART, AUDIO (R47.1 U1.N5), [03] - CONNECTORS (J2.14)
I2C1_SDA: [09] - CPU - UART, AUDIO (R46.1 U1.N6), [03] - CONNECTORS (J2.12)
I2C2_SCL: [06] - CPU - HDMI, LVDS (R28.1 U1.U5), [03] - CONNECTORS (J1.36)
I2C2_SDA: [06] - CPU - HDMI, LVDS (R29.1 U1.T7), [03] - CONNECTORS (J1.38)
I2C3_SCL: [06] - CPU - HDMI, LVDS (R31.1 U1.F21), [08] - CPU - SPI, I2C, SD, MMC (R157.2), [03] - CONNECTORS (J2.19)
I2C3_SDA: [06] - CPU - HDMI, LVDS (R32.1 U1.D24), [08] - CPU - SPI, I2C, SD, MMC (R156.2), [03] - CONNECTORS (J2.17)
JTAG_nTRST: [03] - CONNECTORS (J2.41), [10] - CPU - JTAG, CONTROL (R62.1 U1.C2)
JTAG_TCK: [03] - CONNECTORS (J2.43), [10] - CPU - JTAG, CONTROL (R92.2)
JTAG_TDI: [03] - CONNECTORS (J2.47), [10] - CPU - JTAG, CONTROL (R90.2)
JTAG_TDO: [03] - CONNECTORS (J2.45), [10] - CPU - JTAG, CONTROL (R161.2)
JTAG_TMS: [03] - CONNECTORS (J2.49), [10] - CPU - JTAG, CONTROL (R64.1 U1.C3)
LVDS0_CABC: [06] - CPU - HDMI, LVDS (R33.1 U1.A17), [03] - CONNECTORS (J2.6)
LVDS0_CLK_N: [06] - CPU - HDMI, LVDS (U1.V4), [03] - CONNECTORS (J2.13)
LVDS0_CLK_P: [06] - CPU - HDMI, LVDS (U1.V3), [03] - CONNECTORS (J2.15)
LVDS0_PWM: [06] - CPU - HDMI, LVDS (U1.F18), [03] - CONNECTORS (J2.5)
LVDS0_TX0_N: [06] - CPU - HDMI, LVDS (U1.U2), [03] - CONNECTORS (J2.2)
LVDS0_TX0_P: [06] - CPU - HDMI, LVDS (U1.U1), [03] - CONNECTORS (J2.4)
LVDS0_TX1_N: [06] - CPU - HDMI, LVDS (U1.U4), [03] - CONNECTORS (J2.8)
LVDS0_TX1_P: [06] - CPU - HDMI, LVDS (U1.U3), [03] - CONNECTORS (J2.10)
LVDS0_TX2_N: [06] - CPU - HDMI, LVDS (U1.V2), [03] - CONNECTORS (J2.1)
LVDS0_TX2_P: [06] - CPU - HDMI, LVDS (U1.V1), [03] - CONNECTORS (J2.3)
LVDS0_TX3_N: [06] - CPU - HDMI, LVDS (U1.W2), [03] - CONNECTORS (J2.7)
LVDS0_TX3_P: [06] - CPU - HDMI, LVDS (U1.W1), [03] - CONNECTORS (J2.9)
ON_OFF: [03] - CONNECTORS (J1.6), [10] - CPU - JTAG, CONTROL (R48.1 U1.D12)
PCIE_RX_N: [05] - CPU - PCIE, SATA (U1.B1), [03] - CONNECTORS (J2.52)
PCIE_RX_P: [05] - CPU - PCIE, SATA (U1.B2), [03] - CONNECTORS (J2.54)
PCIE_TX_N: [05] - CPU - PCIE, SATA (C63.2), [03] - CONNECTORS (J2.51)
PCIE_TX_P: [05] - CPU - PCIE, SATA (C65.2), [03] - CONNECTORS (J2.53)
PCIE_WAKE: [05] - CPU - PCIE, SATA (U1.P3), [03] - CONNECTORS (J2.39)
PMIC_ON_REQ: [10] - CPU - JTAG, CONTROL (R73.1 U1.D11), [15] - PWR 3V3, 1V375 (Q8.1)
POK_1V375: [15] - PWR 3V3, 1V375 (R108.1), [16] - PWR 2V5, 1V5 (U13.27)
POK_2V5: [15] - PWR 3V3, 1V375 (U11.14), [16] - PWR 2V5, 1V5 (R163.1)
POK_3V3: [10] - CPU - JTAG, CONTROL (U6.3 U7.4), [13] - ETHERNET PHY (U9.9), [14] - SPI FLASH, LEDS (Q1.1), [15] - PWR 3V3, 1V375 (R107.1)
RGMII_INT: [07] - CPU - USB, ETHERNET (R88.2 U1.W22), [13] - ETHERNET PHY (R89.1 U8.38)
RGMII_MDC: [07] - CPU - USB, ETHERNET (U1.V20), [13] - ETHERNET PHY (R85.1 R87.1)
RGMII_MDIO: [07] - CPU - USB, ETHERNET (U1.V23), [13] - ETHERNET PHY (R86.1 R162.1)
RGMII_RSTn: [10] - CPU - JTAG, CONTROL (D1.2 R65.2), [13] - ETHERNET PHY (R75.1 U8.42)
RGMII_RXCLK: [07] - CPU - USB, ETHERNET (U1.B25), [13] - ETHERNET PHY (R83.1)
RGMII_RXD0: [07] - CPU - USB, ETHERNET (U1.C24), [13] - ETHERNET PHY (R98.1 U8.32)
RGMII_RXD1: [07] - CPU - USB, ETHERNET (U1.B23), [13] - ETHERNET PHY (R97.1 U8.31)
RGMII_RXD2: [07] - CPU - USB, ETHERNET (U1.B24), [13] - ETHERNET PHY (R96.1 U8.28)
RGMII_RXD3: [07] - CPU - USB, ETHERNET (U1.D23), [13] - ETHERNET PHY (R95.1 U8.27)
RGMII_RXDV: [07] - CPU - USB, ETHERNET (U1.D22), [13] - ETHERNET PHY (R91.1 U8.33)
RGMII_TXCLK: [07] - CPU - USB, ETHERNET (R35.2), [13] - ETHERNET PHY (U8.24)
RGMII_TXD0: [07] - CPU - USB, ETHERNET (U1.C22), [13] - ETHERNET PHY (U8.19)
RGMII_TXD1: [07] - CPU - USB, ETHERNET (U1.F20), [13] - ETHERNET PHY (U8.20)
RGMII_TXD2: [07] - CPU - USB, ETHERNET (U1.E21), [13] - ETHERNET PHY (U8.21)
RGMII_TXD3: [07] - CPU - USB, ETHERNET (U1.A24), [13] - ETHERNET PHY (U8.22)
RGMII_TXEN: [07] - CPU - USB, ETHERNET (U1.C23), [13] - ETHERNET PHY (U8.25)
RSTINn: [03] - CONNECTORS (J1.8), [10] - CPU - JTAG, CONTROL (R68.1 U7.1)
RSTOUTn: [03] - CONNECTORS (J1.7), [10] - CPU - JTAG, CONTROL (R51.2 R70.2)
SATA_RX_N: [05] - CPU - PCIE, SATA (C69.2), [03] - CONNECTORS (J2.58)
SATA_RX_P: [05] - CPU - PCIE, SATA (C70.2), [03] - CONNECTORS (J2.60)
SATA_TX_N: [05] - CPU - PCIE, SATA (C71.2), [03] - CONNECTORS (J2.57)
SATA_TX_P: [05] - CPU - PCIE, SATA (C72.2), [03] - CONNECTORS (J2.59)
SD2_ACT: [08] - CPU - SPI, I2C, SD, MMC (U1.T3), [03] - CONNECTORS (J2.11)
SD2_CD: [08] - CPU - SPI, I2C, SD, MMC (R42.1 U1.F16), [03] - CONNECTORS (J2.38)
SD2_CLK: [08] - CPU - SPI, I2C, SD, MMC (R66.2), [03] - CONNECTORS (J2.36)
SD2_CMD: [08] - CPU - SPI, I2C, SD, MMC (R41.1 R52.2), [03] - CONNECTORS (J2.21)
SD2_DATA0: [08] - CPU - SPI, I2C, SD, MMC (U1.A22), [03] - CONNECTORS (J2.26)
SD2_DATA1: [08] - CPU - SPI, I2C, SD, MMC (U1.E20), [03] - CONNECTORS (J2.23)
SD2_DATA2: [08] - CPU - SPI, I2C, SD, MMC (U1.A23), [03] - CONNECTORS (J2.28)
SD2_DATA3: [08] - CPU - SPI, I2C, SD, MMC (U1.B22), [03] - CONNECTORS (J2.25)
SD2_DATA4: [08] - CPU - SPI, I2C, SD, MMC (U1.A19), [03] - CONNECTORS (J2.30)
SD2_DATA5: [08] - CPU - SPI, I2C, SD, MMC (U1.B18), [03] - CONNECTORS (J2.27)
SD2_DATA6: [08] - CPU - SPI, I2C, SD, MMC (U1.E17), [03] - CONNECTORS (J2.32)
SD2_DATA7: [08] - CPU - SPI, I2C, SD, MMC (U1.C18), [03] - CONNECTORS (J2.29)
SD2_WP: [08] - CPU - SPI, I2C, SD, MMC (R43.1 U1.D17), [03] - CONNECTORS (J2.34)
SD3_CD: [08] - CPU - SPI, I2C, SD, MMC (R39.1 U1.A18), [03] - CONNECTORS (J1.34)
SD3_CLK: [08] - CPU - SPI, I2C, SD, MMC (R50.2), [03] - CONNECTORS (J1.27)
SD3_CMD: [08] - CPU - SPI, I2C, SD, MMC (R1.2 R38.1), [03] - CONNECTORS (J1.33)
SD3_DATA0: [08] - CPU - SPI, I2C, SD, MMC (U1.E14), [03] - CONNECTORS (J1.29)
SD3_DATA1: [08] - CPU - SPI, I2C, SD, MMC (U1.F14), [03] - CONNECTORS (J1.30)
SD3_DATA2: [08] - CPU - SPI, I2C, SD, MMC (U1.A15), [03] - CONNECTORS (J1.31)
SD3_DATA3: [08] - CPU - SPI, I2C, SD, MMC (U1.B15), [03] - CONNECTORS (J1.32)
SD3_WP: [08] - CPU - SPI, I2C, SD, MMC (R40.1 U1.C17), [03] - CONNECTORS (J1.25)
TRD0_N: [03] - CONNECTORS (J1.57), [13] - ETHERNET PHY (U8.3)
TRD0_P: [03] - CONNECTORS (J1.59), [13] - ETHERNET PHY (U8.2)
TRD1_N: [03] - CONNECTORS (J1.51), [13] - ETHERNET PHY (U8.6)
TRD1_P: [03] - CONNECTORS (J1.53), [13] - ETHERNET PHY (U8.5)
TRD2_N: [03] - CONNECTORS (J1.58), [13] - ETHERNET PHY (U8.8)
TRD2_P: [03] - CONNECTORS (J1.60), [13] - ETHERNET PHY (U8.7)
TRD3_N: [03] - CONNECTORS (J1.52), [13] - ETHERNET PHY (U8.11)
TRD3_P: [03] - CONNECTORS (J1.54), [13] - ETHERNET PHY (U8.10)
UART1_CTS: [09] - CPU - UART, AUDIO (U1.G21), [03] - CONNECTORS (J1.11)
UART1_DCD: [09] - CPU - UART, AUDIO (U1.D25), [03] - CONNECTORS (J1.16)
UART1_DSR: [09] - CPU - UART, AUDIO (U1.G22), [03] - CONNECTORS (J1.9)
UART1_DTR: [09] - CPU - UART, AUDIO (U1.F22), [03] - CONNECTORS (J1.15)
UART1_RI: [09] - CPU - UART, AUDIO (U1.F23), [03] - CONNECTORS (J1.10)
UART1_RTS: [09] - CPU - UART, AUDIO (U1.G20), [03] - CONNECTORS (J1.13)
UART1_RXD: [09] - CPU - UART, AUDIO (U1.M3), [03] - CONNECTORS (J1.14)
UART1_TXD: [09] - CPU - UART, AUDIO (U1.M1), [03] - CONNECTORS (J1.12)
UART2_CTS: [09] - CPU - UART, AUDIO (U1.B20), [03] - CONNECTORS (J2.31)
UART2_RTS: [09] - CPU - UART, AUDIO (U1.C19), [03] - CONNECTORS (J2.33)
UART2_RXD: [09] - CPU - UART, AUDIO (U1.E18), [03] - CONNECTORS (J2.35)
UART2_TXD: [09] - CPU - UART, AUDIO (U1.D19), [03] - CONNECTORS (J2.37)
USB0_ID: [07] - CPU - USB, ETHERNET (U1.T4), [03] - CONNECTORS (J1.20)
USB0_N: [07] - CPU - USB, ETHERNET (U1.B6), [03] - CONNECTORS (J1.22)
USB0_P: [07] - CPU - USB, ETHERNET (U1.A6), [03] - CONNECTORS (J1.24)
USB0_PWR_EN: [07] - CPU - USB, ETHERNET (U1.E23), [03] - CONNECTORS (J1.26)
USB1_N: [07] - CPU - USB, ETHERNET (U1.F10), [03] - CONNECTORS (J2.40)
USB1_P: [07] - CPU - USB, ETHERNET (U1.E10), [03] - CONNECTORS (J2.42)
USB1_PWR_EN: [07] - CPU - USB, ETHERNET (U1.H21), [03] - CONNECTORS (J2.44)
USB_OC: [07] - CPU - USB, ETHERNET (R100.1 U1.H20 U1.J20), [03] - CONNECTORS (J1.28)
USER_LED: [10] - CPU - JTAG, CONTROL (U1.T1), [14] - SPI FLASH, LEDS (Q2.1 R115.1)

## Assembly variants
Prototype: not fitted FB8 Q5 Q8 Q9 R24 R51 R53 R54 R58 R65 R71 R77 R79 R87 R103 R105 R111 R117 R118 R120 R131 R133 R135 R137 R141 R142 R155 R156 R157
